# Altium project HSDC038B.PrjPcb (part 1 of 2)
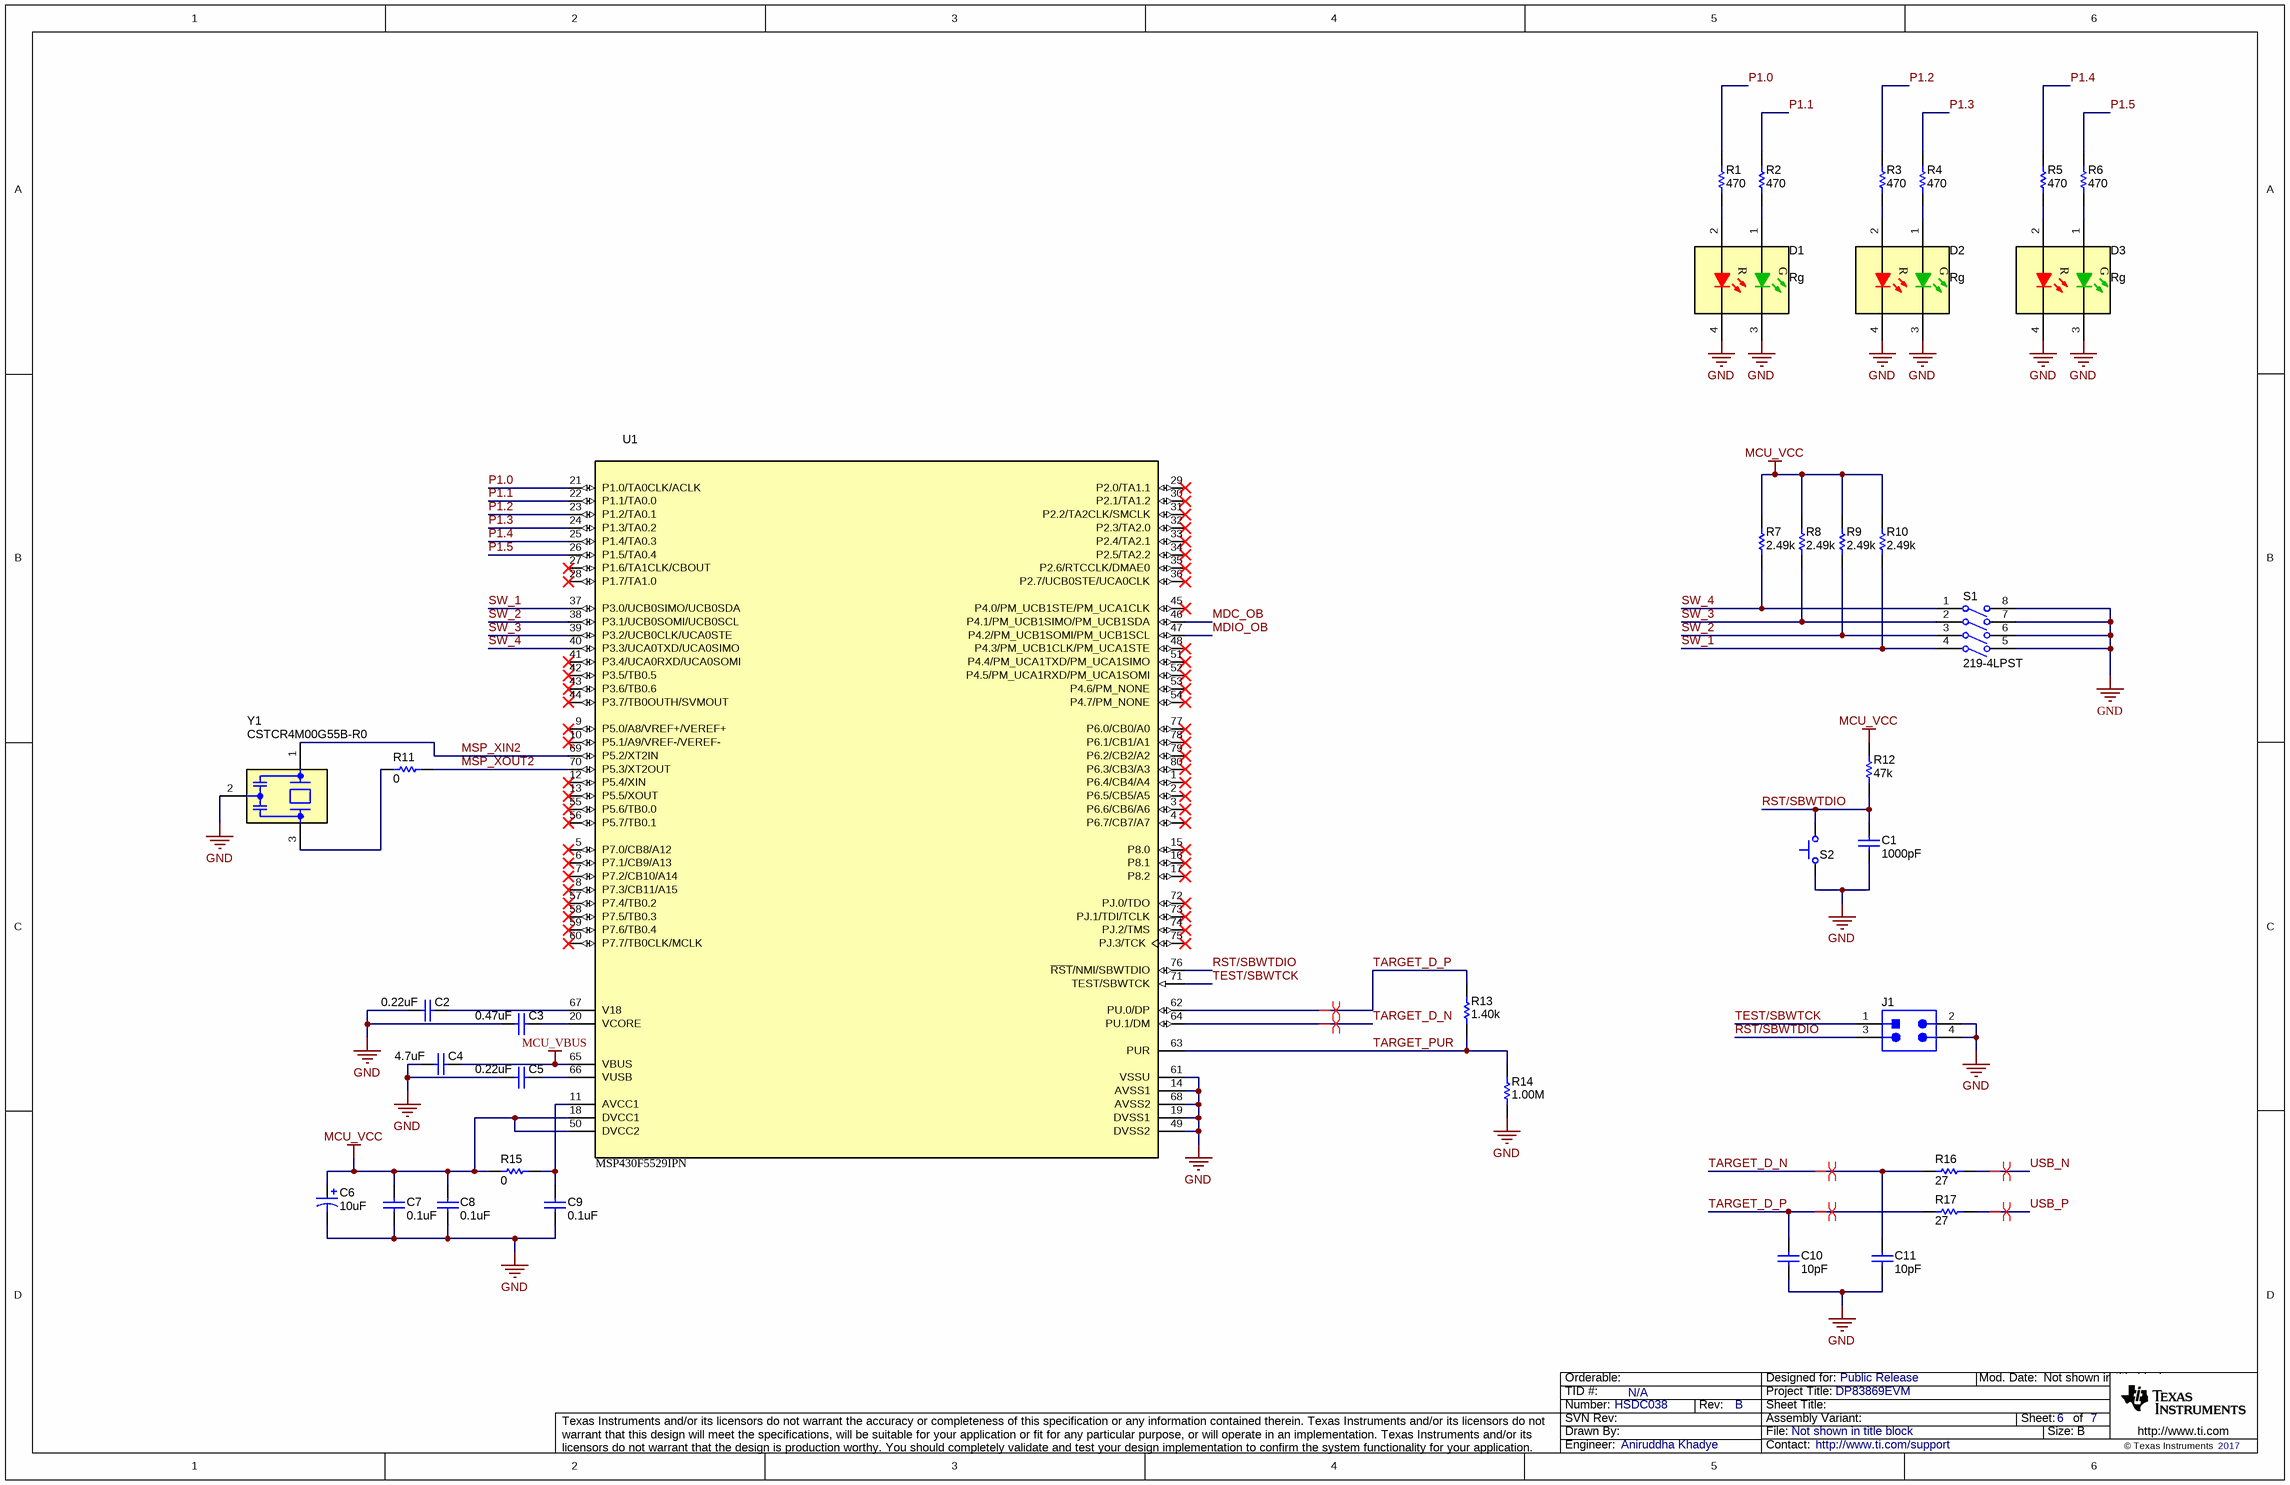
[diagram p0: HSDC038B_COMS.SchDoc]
CopyrightYear: 2017; PCB_Layout: Mitch Morse; PCB_Rev: B; PRJ_Customer: Public Release; PRJ_Engineer: Aniruddha Khadye; PRJ_Number: HSDC038; PRJ_Title: DP83869EVM; SCH_Rev: B; TechSupport: http://www.ti.com/support; TID: N/A
7 sheets, 350 parts. Net scope: global (net labels, ports and power ports of the same name join across sheets).
Board file: HSDC038B.PcbDoc
Sheets:
  HSDC038B_COMS.SchDoc
  HSDC038B_Configuration_Pins.SchDoc
  HSDC038B_CoverSheet.SchDoc
  HSDC038B_DP83869.SchDoc
  HSDC038B_Hardware.SchDoc
  HSDC038B_Magnetics.SchDoc
  HSDC038B_Power_Supply.SchDoc

## Sheet HSDC038B_COMS.SchDoc
size 431 x 279 mm; Date: Not shown in title block; ApprovedBy: Not shown in title block; CheckedBy: Not shown in title block; Author: Not shown in title block; CompanyName: Not shown in title block; Engineer: Not shown in title block; Organization: Not shown in title block; Address1: Not shown in title block; Address2: Not shown in title block; Address3: Not shown in title block; Address4: Not shown in title block; DocumentNumber: 6; Revision: Use project parameter SCH_Rev; SheetNumber: 6; SheetTotal: 7; PageSetup: Record=PageOptions¦CenterHorizontal=True¦CenterVertical=True¦PrintScale=1.00¦XCorrection=1.00¦YCorrection=1.00¦PrintKind=0¦BorderSize=5000000¦LeftOffset=0¦BottomOffset=0¦Orientation=2¦PaperLength=1000¦PaperWidth=1000¦Scale=100¦PaperSource=15¦PrintQuality=600¦MediaType=1¦DitherType=10¦PaperKind=Letter¦PrintScaleMode=1

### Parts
C1  ValueDisplayed: 1000pF  [0402]  (hidden comment: C1005NP01H102J050BA)
C2  ValueDisplayed: 0.22uF  [0603]  (hidden comment: C1608X5R1H224K080AB)
C3  ValueDisplayed: 0.47uF  [0603]  (hidden comment: C1608X6S1H474K080AB)
C4  ValueDisplayed: 4.7uF  [0603]  (hidden comment: C1608X5R1V475K080AC)
C5  ValueDisplayed: 0.22uF  [0603]  (hidden comment: C1608X5R1H224K080AB)
C6  ValueDisplayed: 10uF  [7343-31]  (hidden comment: TPSD106K035R0125)
C7  ValueDisplayed: 0.1uF  [0402]  (hidden comment: GRM155R71C104KA88D)
C8  ValueDisplayed: 0.1uF  [0402]  (hidden comment: GRM155R71C104KA88D)
C9  ValueDisplayed: 0.1uF  [0402]  (hidden comment: GRM155R71C104KA88D)
C10  ValueDisplayed: 10pF  [0603]  (hidden comment: CGA3E2NP01H100D080AA)
C11  ValueDisplayed: 10pF  [0603]  (hidden comment: CGA3E2NP01H100D080AA)
D1  value Rg  [HSMF-C165_RG]  (hidden comment: HSMF-C165)
D2  value Rg  [HSMF-C165_RG]  (hidden comment: HSMF-C165)
D3  value Rg  [HSMF-C165_RG]  (hidden comment: HSMF-C165)
J1  TSW-102-07-G-D  [TSW-102-07-G-D]  (value not drawn)
R1  ValueDisplayed: 470  [0402]  (hidden comment: CRCW0402470RJNED)
R2  ValueDisplayed: 470  [0402]  (hidden comment: CRCW0402470RJNED)
R3  ValueDisplayed: 470  [0402]  (hidden comment: CRCW0402470RJNED)
R4  ValueDisplayed: 470  [0402]  (hidden comment: CRCW0402470RJNED)
R5  ValueDisplayed: 470  [0402]  (hidden comment: CRCW0402470RJNED)
R6  ValueDisplayed: 470  [0402]  (hidden comment: CRCW0402470RJNED)
R7  ValueDisplayed: 2.49k  [0402]  (hidden comment: CRCW04022K49FKED)
R8  ValueDisplayed: 2.49k  [0402]  (hidden comment: CRCW04022K49FKED)
R9  ValueDisplayed: 2.49k  [0402]  (hidden comment: CRCW04022K49FKED)
R10  ValueDisplayed: 2.49k  [0402]  (hidden comment: CRCW04022K49FKED)
R11  ValueDisplayed: 0  [0402]  (hidden comment: CRCW04020000Z0ED)
R12  ValueDisplayed: 47k  [0402]  (hidden comment: CRCW040247K0JNED)
R13  ValueDisplayed: 1.40k  [0402]  (hidden comment: CRCW04021K40FKED)
R14  ValueDisplayed: 1.00M  [0402]  (hidden comment: CRCW04021M00FKED)
R15  ValueDisplayed: 0  [0402]  (hidden comment: CRCW04020000Z0ED)
R16  ValueDisplayed: 27  [0402]  (hidden comment: CRCW040227R0JNED)
R17  ValueDisplayed: 27  [0402]  (hidden comment: CRCW040227R0JNED)
S1  219-4LPST  [SW_219-4LPST]
S2  KSR221GLFS  [KSR]  (value not drawn)
U1  MSP430F5529IPN  [PN0080A_N]
Y1  CSTCR4M00G55B-R0  [Murata_CSTCR_G]

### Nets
GND: C1.1 C2.2 C3.2 C4.1 C5.2 C6.2(-) C7.1 C8.1 C9.1 C10.1 C11.1 D1.3(K) D1.4(K) D2.3(K) D2.4(K) D3.3(K) D3.4(K) J1.2 J1.4 R14.2 S1.5(B4) S1.6(B3) S1.7(B2) S1.8(B1) S2.1 U1.14(AVSS1) U1.19(DVSS1) U1.49(DVSS2) U1.61(VSSU) U1.68(AVSS2) Y1.2(GND)
MCU_VBUS: C4.2 U1.65(VBUS)
MCU_VCC: C6.1(+) C7.2 C8.2 R7.1 R8.1 R9.1 R10.1 R12.1 R15.1 U1.18(DVCC1) U1.50(DVCC2)
MDC_OB: U1.46(P4.1/PM_UCB1SIMO/PM_UCB1SDA)
MDIO_OB: U1.47(P4.2/PM_UCB1SOMI/PM_UCB1SCL)
MSP_XIN2: U1.69(P5.2/XT2IN) Y1.1(In)
MSP_XOUT2: R11.2 U1.70(P5.3/XT2OUT)
P1.0: R1.2 U1.21(P1.0/TA0CLK/ACLK)
P1.1: R2.2 U1.22(P1.1/TA0.0)
P1.2: R3.2 U1.23(P1.2/TA0.1)
P1.3: R4.2 U1.24(P1.3/TA0.2)
P1.4: R5.2 U1.25(P1.4/TA0.3)
P1.5: R6.2 U1.26(P1.5/TA0.4)
RST/SBWTDIO: C1.2 J1.3 R12.2 S2.2 U1.76(~{RST}/NMI/SBWTDIO)
SW_1: R10.2 S1.4(A4) U1.37(P3.0/UCB0SIMO/UCB0SDA)
SW_2: R9.2 S1.3(A3) U1.38(P3.1/UCB0SOMI/UCB0SCL)
SW_3: R8.2 S1.2(A2) U1.39(P3.2/UCB0CLK/UCA0STE)
SW_4: R7.2 S1.1(A1) U1.40(P3.3/UCA0TXD/UCA0SIMO)
TARGET_D_N: C11.2 R16.1 U1.64(PU.1/DM)
TARGET_D_P: C10.2 R13.2 R17.1 U1.62(PU.0/DP)
TARGET_PUR: R13.1 R14.1 U1.63(PUR)
TEST/SBWTCK: J1.1 U1.71(TEST/SBWTCK)
USB_N: R16.2
USB_P: R17.2
NetC2_1: C2.1 U1.67(V18)
NetC3_1: C3.1 U1.20(VCORE)
NetC5_1: C5.1 U1.66(VUSB)
NetC9_2: C9.2 R15.2 U1.11(AVCC1)
NetD1_1: D1.1(A) R2.1
NetD1_2: D1.2(A) R1.1
NetD2_1: D2.1(A) R4.1
NetD2_2: D2.2(A) R3.1
NetD3_1: D3.1(A) R6.1
NetD3_2: D3.2(A) R5.1
NetR11_1: R11.1 Y1.3(Out)

Not connected (* = marked no-connect by the designer): U1 1(P6.4/CB4/A4)* 2(P6.5/CB5/A5)* 3(P6.6/CB6/A6)* 4(P6.7/CB7/A7)* 5(P7.0/CB8/A12)* 6(P7.1/CB9/A13)* 7(P7.2/CB10/A14)* 8(P7.3/CB11/A15)* 9(P5.0/A8/VREF+/VEREF+)* 10(P5.1/A9/VREF-/VEREF-)* 12(P5.4/XIN)* 13(P5.5/XOUT)* 15(P8.0)* 16(P8.1)* 17(P8.2)* 27(P1.6/TA1CLK/CBOUT)* 28(P1.7/TA1.0)* 29(P2.0/TA1.1)* 30(P2.1/TA1.2)* 31(P2.2/TA2CLK/SMCLK)* 32(P2.3/TA2.0)* 33(P2.4/TA2.1)* 34(P2.5/TA2.2)* 35(P2.6/RTCCLK/DMAE0)* 36(P2.7/UCB0STE/UCA0CLK)* 41(P3.4/UCA0RXD/UCA0SOMI)* 42(P3.5/TB0.5)* 43(P3.6/TB0.6)* 44(P3.7/TB0OUTH/SVMOUT)* 45(P4.0/PM_UCB1STE/PM_UCA1CLK)* 48(P4.3/PM_UCB1CLK/PM_UCA1STE)* 51(P4.4/PM_UCA1TXD/PM_UCA1SIMO)* 52(P4.5/PM_UCA1RXD/PM_UCA1SOMI)* 53(P4.6/PM_NONE)* 54(P4.7/PM_NONE)* 55(P5.6/TB0.0)* 56(P5.7/TB0.1)* 57(P7.4/TB0.2)* 58(P7.5/TB0.3)* 59(P7.6/TB0.4)* 60(P7.7/TB0CLK/MCLK)* 72(PJ.0/TDO)* 73(PJ.1/TDI/TCLK)* 74(PJ.2/TMS)* 75(PJ.3/TCK)* 77(P6.0/CB0/A0)* 78(P6.1/CB1/A1)* 79(P6.2/CB2/A2)* 80(P6.3/CB3/A3)*

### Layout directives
differential pair: TARGET_D_N, TARGET_D_P, USB_N, USB_P

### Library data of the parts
C1 = CMP-0006254-2: CAP, CERM, 1000 pF, 50 V, +/- 5%, C0G/NP0, 0402; Manufacturer: TDK; Polarized: N; Value: 1000pF; U/M: EA; Cap_F: 1nF; Value1: Unknown; VDC_V: 50V; TaMin_C: -55°C; TaMax_C: 150°C; SizeArea_mm2: 0.5; SizeAreaWB_mm2: 3; SizeX_mm: 1; SizeZ_mm: 0.6; AEC Category: Q200
C2 C5 = CMP-0007013-5: CAP, CERM, 0.22 uF, 50 V, +/- 10%, X5R, 0603; Manufacturer: TDK; Polarized: N; Value: 0.22uF; U/M: EA; Cap_F: 220nF; ESR_ohm: 0.021699; Value1: 0.021699 ohm; VDC_V: 50V; IRMS_A: 1.12496A; TaMin_C: -55°C; TaMax_C: 85°C; SizeArea_mm2: 1.28; SizeAreaWB_mm2: 4.68; SizeX_mm: 1.6; SizeY_mm: 0.8; SizeZ_mm: 1; AEC Category: Q200
C3 = CMP-0007033-4: CAP, CERM, 0.47 uF, 50 V, +/- 10%, X6S, 0603; Manufacturer: TDK; Polarized: N; Value: 0.47uF; U/M: EA; Cap_F: 470nF; ESR_ohm: 0.010974; Value1: 0.010974 ohm; VDC_V: 50V; IRMS_A: 1.57483A; TaMin_C: -55°C; TaMax_C: 105°C; SizeArea_mm2: 1.28; SizeAreaWB_mm2: 4.68; SizeX_mm: 1.6; SizeY_mm: 0.8; SizeZ_mm: 1; AEC Category: Q200
C4 = CMP-0007022-5: CAP, CERM, 4.7 uF, 35 V, +/- 10%, X5R, 0603; Manufacturer: TDK; Polarized: N; Value: 4.7uF; U/M: EA; Cap_F: 4.7µF; ESR_ohm: 3.728m; Value1: 0.003728 ohm; VDC_V: 35V; IRMS_A: 2.69359A; TaMin_C: -55°C; TaMax_C: 85°C; SizeArea_mm2: 1.28; SizeAreaWB_mm2: 4.68; SizeX_mm: 1.6; SizeY_mm: 0.8; SizeZ_mm: 1; AEC Category: Q200
C6 = CMP-0011855-2: CAP, TA, 10 uF, 35 V, +/- 10%, 0.125 ohm, SMD; Manufacturer: AVX; Polarized: Y; CompType: Capacitor; Value: 10uF; U/M: EA; Cap_F: 10µF; VDC_V: 35V; ESR_ohm: 1.25d; IRMS_A: 9.86dA; TaMin_C: -55°C; TaMax_C: 125°C; Cap_Case: D; AEC Category: Q200; SizeArea_mm2: 31.39; SizeAreaWB_mm2: 58.59; SizeX_mm: 7.3; SizeY_mm: 4.3; SizeZ_mm: 3.1
C7-C9 = CMP-0006641-2: CAP, CERM, 0.1 uF, 16 V, +/- 10%, X7R, 0402; Manufacturer: MuRata; Polarized: N; Value: 0.1uF; U/M: EA; Cap_F: 100nF; Value1: Unknown; VDC_V: 16V; TaMin_C: -55°C; TaMax_C: 125°C; AEC Category: Q200; SizeArea_mm2: 0.5; SizeAreaWB_mm2: 3; SizeX_mm: 1; SizeZ_mm: 0.6
C10 C11 = CMP-0007074-4: CAP, CERM, 10 pF, 50 V, +/- 5%, C0G/NP0, 0603; Manufacturer: TDK; Polarized: N; Value: 10pF; U/M: EA; Value1: Unknown; VDC_V: 50V; TaMin_C: -55°C; TaMax_C: 150°C; SizeArea_mm2: 1.28; SizeAreaWB_mm2: 4.68; SizeX_mm: 1.6; SizeY_mm: 0.8; SizeZ_mm: 1; AEC Category: Q200
D1-D3 = CMP-0002934-2: LED, Rg, SMD; Manufacturer: Avago; Vf_V: 2.2V; Io_A: 20mA; Vr_V: 5V; Ir_A: 100µA; Tjmax_C: 85°C; Value1: W; LuminousIntensity_IV: 20; Angle: 120; U/M: EA
J1 = CMP-0075404-1: Header, 100mil, 2x2, Gold, TH; Manufacturer: Samtec; Pitch_mm: 2.54; Gender: Male; Shrouded: N; Row_Count: 2; Current_A: 6.3A; Voltage_V: 550V; Cert_CSA: Y; CNHeader: True; CT: False; Green_Lifecycle: Active; Green_REACh: Passed
R1-R6 = CMP-0026934-3: RES, 470, 5%, 0.063 W, AEC-Q200 Grade 0, 0402; Manufacturer: Vishay-Dale; Value: 470; Value_Code: 470R; Power_W: 63mW; Value2: 0.063W; VDC_V: 50V; TempCo: 200 ppm/C; EIA_Code: E24; AEC Category: Q200; AEC Grade: 0; AEC Qualified: Y; SizeArea_mm2: 0.5; SizeX_mm: 1; SizeZ_mm: 0.6
R7-R10 = CMP-0026237-2: RES, 2.49 k, 1%, 0.063 W, AEC-Q200 Grade 0, 0402; Manufacturer: Vishay-Dale; Value: 2.49k; Value_Code: 2k49; Power_W: 63mW; Value2: 0.063W; VDC_V: 50V; TempCo: 100 ppm/C; EIA_Code: E96; AEC Category: Q200; AEC Qualified: Y; AEC Grade: 0; SizeArea_mm2: 0.5; SizeX_mm: 1; SizeZ_mm: 0.6
R11 R15 = CMP-0026822-3: RES, 0, 5%, 0.063 W, AEC-Q200 Grade 0, 0402; Manufacturer: Vishay-Dale; Value: 0; Value_Code: 0000; Power_W: 63mW; Value2: 0.063W; VDC_V: 50V; TempCo: 200 ppm/C; EIA_Code: E24; AEC Category: Q200; AEC Qualified: Y; SizeArea_mm2: 0.5; SizeX_mm: 1; SizeZ_mm: 0.6
R12 = CMP-0026935-3: RES, 47 k, 5%, 0.063 W, AEC-Q200 Grade 0, 0402; Manufacturer: Vishay-Dale; Value: 47k; Value_Code: 47k0; Power_W: 63mW; Value2: 0.063W; VDC_V: 50V; TempCo: 200 ppm/C; EIA_Code: E24; AEC Category: Q200; AEC Qualified: Y; AEC Grade: 0; SizeArea_mm2: 0.5; SizeX_mm: 1; SizeZ_mm: 0.6
R13 = CMP-0026085-3: RES, 1.40 k, 1%, 0.063 W, AEC-Q200 Grade 0, 0402; Manufacturer: Vishay-Dale; Value: 1.40k; Res_ohm: 1.4k; Value_Code: 1k40; Power_W: 63mW; Value2: 0.063W; VDC_V: 50V; TempCo: 100 ppm/C; EIA_Code: E96; AEC Category: Q200; AEC Qualified: Y; AEC Grade: 0; SizeArea_mm2: 0.5; SizeX_mm: 1; SizeZ_mm: 0.6
R14 = CMP-0026100-2: RES, 1.00 M, 1%, 0.063 W, AEC-Q200 Grade 0, 0402; Manufacturer: Vishay-Dale; Value: 1.00Meg; Res_ohm: 1M; Value_Code: 1M00; Power_W: 63mW; Value2: 0.063W; VDC_V: 50V; TempCo: 100 ppm/C; EIA_Code: E96; AEC Category: Q200; AEC Qualified: Y; AEC Grade: 0; SizeArea_mm2: 0.5; SizeX_mm: 1; SizeZ_mm: 0.6
R16 R17 = CMP-0026888-3: RES, 27, 5%, 0.063 W, AEC-Q200 Grade 0, 0402; Manufacturer: Vishay-Dale; Value: 27; Value_Code: 27R0; Power_W: 63mW; Value2: 0.063W; VDC_V: 50V; TempCo: 200 ppm/C; EIA_Code: E24; AEC Category: Q200; AEC Qualified: Y; AEC Grade: 0; SizeArea_mm2: 0.5; SizeX_mm: 1; SizeZ_mm: 0.6
S1 = CMP-0002176-2: Switch, SPST 4 Pos, Top Actuated, SMT; Manufacturer: CTS Electrocomponents; VDC_V: 50V; SwitchFunction: Off-On; PositionCount: 4; CurrentRating_mA: 100A
S2 = CMP-0002170-2: Switch, Normally open, 2.3N force, 200k operations, SMD; Manufacturer: C&K Components; Circuit: SPST Switch; VDC_V: 32V; SwitchFunction: Off-Mom; PositionCount: 1; CurrentRating_mA: 1.001kA
U1 = CMP-0038965-1: 25 MHz Mixed Signal Microcontroller with 128 KB Flash, 8192 B SRAM and 63 GPIOs, -40 to 85 degC, 80-pin QFP (PN), Green (RoHS & no Sb/Br); Manufacturer: Texas Instruments; ADC: 12-bit SAR; ADC Channels: 16; Brown Out Reset: Yes; DMA: 3; Flash(KB): 128; Frequency(MHz): 25; GPIO: 63; Multiplier: 32x32; SRAM(B): 8192; SubFamily: 5 Series; Timers - 16-bit: 4; USB: 1; USCI_A (UART/LIN/IrDA/SPI): 2
Y1 = CMP-0084387-1: Resonator, 4 MHz, 39 pF, AEC-Q200 Grade 1, SMD; Manufacturer: MuRata; SizeAreaWB_mm2: 16.5; SizeArea_mm2: 9; SizeX_mm: 4.5; SizeY_mm: 2; SizeZ_mm: 1.2; TaMin_C: -40°C; TaMax_C: 125°C; Frequency_Fixed: 4MHz; AEC Category: Q200; AEC Grade: 1; AEC Qualified: Y; Load Capacitance: 39 pF

## Sheet HSDC038B_Configuration_Pins.SchDoc
size 431 x 279 mm; Date: Not shown in title block; ApprovedBy: Not shown in title block; CheckedBy: Not shown in title block; Author: Not shown in title block; CompanyName: Not shown in title block; Engineer: Not shown in title block; Organization: Not shown in title block; Address1: Not shown in title block; Address2: Not shown in title block; Address3: Not shown in title block; Address4: Not shown in title block; DocumentNumber: 3; Revision: Use project parameter SCH_Rev; SheetNumber: 3; SheetTotal: 7; PageSetup: Record=PageOptions¦CenterHorizontal=True¦CenterVertical=True¦PrintScale=1.00¦XCorrection=1.00¦YCorrection=1.00¦PrintKind=0¦BorderSize=5000000¦LeftOffset=0¦BottomOffset=0¦Orientation=2¦PaperLength=1000¦PaperWidth=1000¦Scale=100¦PaperSource=15¦PrintQuality=600¦MediaType=1¦DitherType=10¦PaperKind=Letter¦PrintScaleMode=1
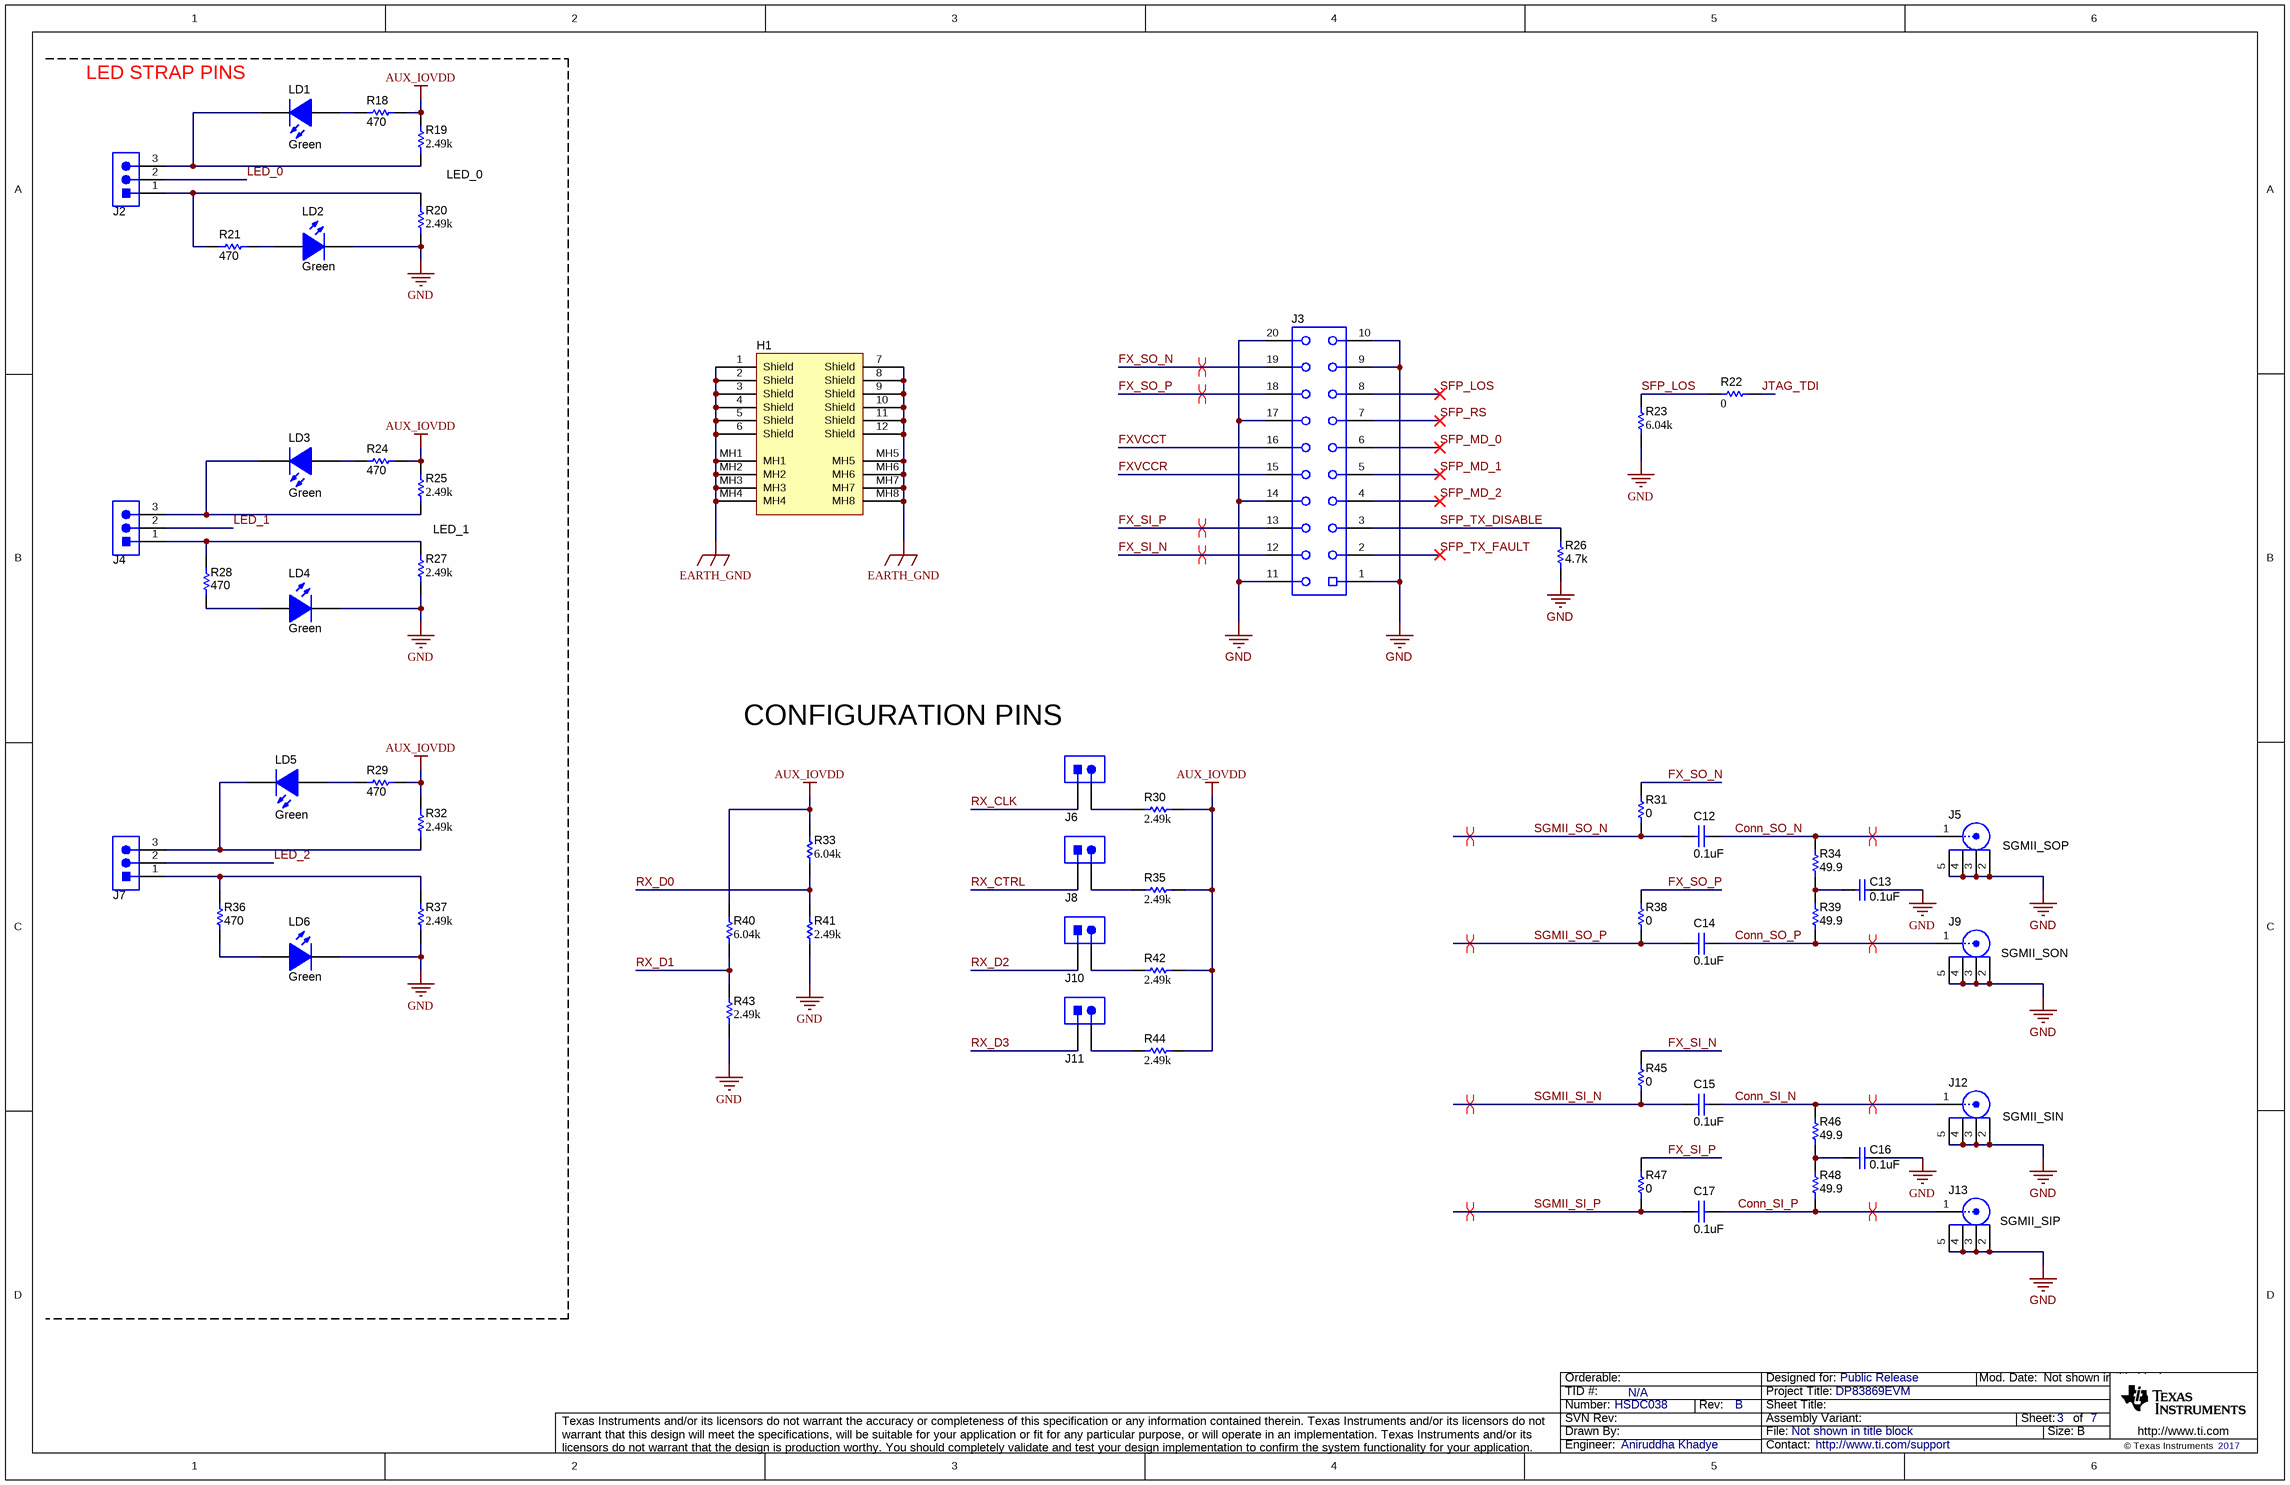
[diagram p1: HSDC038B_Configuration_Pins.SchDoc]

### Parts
C12  ValueDisplayed: 0.1uF  [0402_065]  (hidden comment: 160R07X104KV4T)
C13  ValueDisplayed: 0.1uF  [0402]  (hidden comment: GRM155R71C104KA88D)
C14  ValueDisplayed: 0.1uF  [0402_065]  (hidden comment: 160R07X104KV4T)
C15  ValueDisplayed: 0.1uF  [0402_065]  (hidden comment: 160R07X104KV4T)
C16  ValueDisplayed: 0.1uF  [0402]  (hidden comment: GRM155R71C104KA88D)
C17  ValueDisplayed: 0.1uF  [0402_065]  (hidden comment: 160R07X104KV4T)
H1  U77-A1118-200T  [Amphenol_U77-A1118-200T]  (value not drawn)
J2  HTSW-103-07-G-S  [Samtec_HTSW-103-07-G-S]  (value not drawn)
J3  1367073-1  [TE_1367073-1]  (value not drawn)
J4  HTSW-103-07-G-S  [Samtec_HTSW-103-07-G-S]  (value not drawn)
J5  901-143-6RFX  [Amphenol_901-143-6RFX]  (value not drawn)
J6  HTSW-102-07-G-S  [Samtec_HTSW-102-07-G-S]  (value not drawn)
J7  HTSW-103-07-G-S  [Samtec_HTSW-103-07-G-S]  (value not drawn)
J8  HTSW-102-07-G-S  [Samtec_HTSW-102-07-G-S]  (value not drawn)
J9  901-143-6RFX  [Amphenol_901-143-6RFX]  (value not drawn)
J10  HTSW-102-07-G-S  [Samtec_HTSW-102-07-G-S]  (value not drawn)
J11  HTSW-102-07-G-S  [Samtec_HTSW-102-07-G-S]  (value not drawn)
J12  901-143-6RFX  [Amphenol_901-143-6RFX]  (value not drawn)
J13  901-143-6RFX  [Amphenol_901-143-6RFX]  (value not drawn)
LD1  value Green  [QTLP630C_Green]  (hidden comment: QTLP630C4TR)
LD2  value Green  [QTLP630C_Green]  (hidden comment: QTLP630C4TR)
LD3  value Green  [QTLP630C_Green]  (hidden comment: QTLP630C4TR)
LD4  value Green  [QTLP630C_Green]  (hidden comment: QTLP630C4TR)
LD5  value Green  [QTLP630C_Green]  (hidden comment: QTLP630C4TR)
LD6  value Green  [QTLP630C_Green]  (hidden comment: QTLP630C4TR)
R18  ValueDisplayed: 470  [0603]  (hidden comment: RC0603FR-07470RL)
R19  ValueDisplayed: 2.49k  [0402]  (hidden comment: CRCW04022K49FKED)
R20  ValueDisplayed: 2.49k  [0402]  (hidden comment: CRCW04022K49FKED)
R21  ValueDisplayed: 470  [0603]  (hidden comment: RC0603FR-07470RL)
R22  ValueDisplayed: 0  [0402]  (hidden comment: ERJ-2GE0R00X)
R23  ValueDisplayed: 6.04k  [0402]  (hidden comment: CRCW04026K04FKED)
R24  ValueDisplayed: 470  [0603]  (hidden comment: RC0603FR-07470RL)
R25  ValueDisplayed: 2.49k  [0402]  (hidden comment: CRCW04022K49FKED)
R26  ValueDisplayed: 4.7k  [0402]  (hidden comment: CRCW04024K70JNED)
R27  ValueDisplayed: 2.49k  [0402]  (hidden comment: CRCW04022K49FKED)
R28  ValueDisplayed: 470  [0603]  (hidden comment: RC0603FR-07470RL)
R29  ValueDisplayed: 470  [0603]  (hidden comment: RC0603FR-07470RL)
R30  ValueDisplayed: 2.49k  [0402]  (hidden comment: CRCW04022K49FKED)
R31  ValueDisplayed: 0  [0402]  (hidden comment: MCR01MZPJ000)
R32  ValueDisplayed: 2.49k  [0402]  (hidden comment: CRCW04022K49FKED)
R33  ValueDisplayed: 6.04k  [0402]  (hidden comment: CRCW04026K04FKED)
R34  ValueDisplayed: 49.9  [0402L]  (hidden comment: CRCW040249R9FKED)
R35  ValueDisplayed: 2.49k  [0402]  (hidden comment: CRCW04022K49FKED)
R36  ValueDisplayed: 470  [0603]  (hidden comment: RC0603FR-07470RL)
R37  ValueDisplayed: 2.49k  [0402]  (hidden comment: CRCW04022K49FKED)
R38  ValueDisplayed: 0  [0402]  (hidden comment: MCR01MZPJ000)
R39  ValueDisplayed: 49.9  [0402L]  (hidden comment: CRCW040249R9FKED)
R40  ValueDisplayed: 6.04k  [0402]  (hidden comment: CRCW04026K04FKED)
R41  ValueDisplayed: 2.49k  [0402]  (hidden comment: CRCW04022K49FKED)
R42  ValueDisplayed: 2.49k  [0402]  (hidden comment: CRCW04022K49FKED)
R43  ValueDisplayed: 2.49k  [0402]  (hidden comment: CRCW04022K49FKED)
R44  ValueDisplayed: 2.49k  [0402]  (hidden comment: CRCW04022K49FKED)
R45  ValueDisplayed: 0  [0402]  (hidden comment: MCR01MZPJ000)
R46  ValueDisplayed: 49.9  [0402L]  (hidden comment: CRCW040249R9FKED)
R47  ValueDisplayed: 0  [0402]  (hidden comment: MCR01MZPJ000)
R48  ValueDisplayed: 49.9  [0402L]  (hidden comment: CRCW040249R9FKED)

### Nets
AUX_IOVDD: R18.1 R19.2 R24.1 R25.2 R29.1 R30.2 R32.2 R33.2 R35.2 R40.2 R42.2 R44.2
EARTH_GND: H1.1(Shield) H1.2(Shield) H1.3(Shield) H1.4(Shield) H1.5(Shield) H1.6(Shield) H1.7(Shield) H1.8(Shield) H1.9(Shield) H1.10(Shield) H1.11(Shield) H1.12(Shield) H1.MH1 H1.MH2 H1.MH3 H1.MH4 H1.MH5 H1.MH6 H1.MH7 H1.MH8
FXVCCR: J3.15
FXVCCT: J3.16
GND: C13.2 C16.2 J3.1 J3.9 J3.10 J3.11 J3.14 J3.17 J3.20 J5.2 J5.3 J5.4 J5.5 J9.2 J9.3 J9.4 J9.5 J12.2 J12.3 J12.4 J12.5 J13.2 J13.3 J13.4 J13.5 LD2.2(K) LD4.2(K) LD6.2(K) R20.1 R23.1 R26.1 R27.1 R37.1 R41.1 R43.1
Conn_SI_N: C15.1 J12.1 R46.2
Conn_SI_P: C17.1 J13.1 R48.1
Conn_SO_N: C12.1 J5.1 R34.2
Conn_SO_P: C14.1 J9.1 R39.1
FX_SI_N: J3.12 R45.2
FX_SI_P: J3.13 R47.2
FX_SO_N: J3.19 R31.2
FX_SO_P: J3.18 R38.2
JTAG_TDI: R22.2
LED_0: J2.2
LED_1: J4.2
LED_2: J7.2
RX_CLK: J6.1
RX_CTRL: J8.1
RX_D0: R33.1 R41.2
RX_D1: R40.1 R43.2
RX_D2: J10.1
RX_D3: J11.1
SFP_LOS: J3.8 R22.1 R23.2
SFP_MD_0: J3.6
SFP_MD_1: J3.5
SFP_MD_2: J3.4
SFP_RS: J3.7
SFP_TX_DISABLE: J3.3 R26.2
SFP_TX_FAULT: J3.2
SGMII_SI_N: C15.2 R45.1
SGMII_SI_P: C17.2 R47.1
SGMII_SO_N: C12.2 R31.1
SGMII_SO_P: C14.2 R38.1
NetC13_1: C13.1 R34.1 R39.2
NetC16_1: C16.1 R46.1 R48.2
NetJ2_1: J2.1 R20.2 R21.1
NetJ2_3: J2.3 LD1.2(K) R19.1
NetJ4_1: J4.1 R27.2 R28.2
NetJ4_3: J4.3 LD3.2(K) R25.1
NetJ6_2: J6.2 R30.1
NetJ7_1: J7.1 R36.2 R37.2
NetJ7_3: J7.3 LD5.2(K) R32.1
NetJ8_2: J8.2 R35.1
NetJ10_2: J10.2 R42.1
NetJ11_2: J11.2 R44.1
NetLD1_1: LD1.1(A) R18.2
NetLD2_1: LD2.1(A) R21.2
NetLD3_1: LD3.1(A) R24.2
NetLD4_1: LD4.1(A) R28.1
NetLD5_1: LD5.1(A) R29.2
NetLD6_1: LD6.1(A) R36.1

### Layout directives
differential pair: Conn_SI_N, Conn_SI_P, Conn_SO_N, Conn_SO_P, FX_SI_N, FX_SI_P, FX_SO_N, FX_SO_P, SGMII_SI_N, SGMII_SI_P, SGMII_SO_N, SGMII_SO_P

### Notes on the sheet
- LED STRAP PINS
- LED_0
- LED_1
- CONFIGURATION PINS
- (near J5) SGMII_SOP
- (near J9) SGMII_SON
- (near J12) SGMII_SIN
- (near J13) SGMII_SIP

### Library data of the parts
C12 C14 C15 C17 = CMP-0006204-2: CAP, CERM, 0.1 uF, 16 V, +/- 10%, X5R, 0402; Manufacturer: Johanson Technology; TaMin_C: -55°C; Polarized: N; SizeAreaWB_mm2: 3; Value1: Unknown; U/M: EA; Value: 0.1uF; TaMax_C: 85°C; SizeZ_mm: 0.65; SizeX_mm: 1; SizeY_mm: 0.5; Cap_Case: 0402; Value2: 16V; CompType: Capacitor; Cap_F: 100nF; AEC Category: Q200
C13 C16 = CMP-0006641-2: as C7 on sheet HSDC038B_COMS
H1 = CMP-0003774-1: SFP Single Cage; Manufacturer: Amphenol Canada
J2 J4 J7 = CMP-0075484-1: Header, 100mil, 3x1, Gold, TH; Manufacturer: Samtec; Green_REACh: Passed; CT: False; Green_Lifecycle: Active; CNHeader: True
J3 = CMP-0054875-1: Receptacle, 0.8mm, 10x2, Gold, R/A, SMT; Manufacturer: TE Connectivity; CNHeader: FALSE; Gender: Female; Pitch_mm: 0.8; Row_Count: 2; RowSpacing_mm: 8.2
J5 J9 J12 J13 = CMP-0055851-2: JACK, SMA, 50 Ohm, Gold, R/A, TH; Manufacturer: Amphenol RF; Gender: Female
J6 J8 J10 J11 = CMP-0075483-1: Header, 100mil, 2x1, Gold, TH; Manufacturer: Samtec; Green_REACh: Passed; CT: False; Green_Lifecycle: Active; CNHeader: True
LD1-LD6 = CMP-0002917-1: LED, Green, SMD; Manufacturer: Everlight; Vf_V: 2.1V; Io_A: 20mA; Vr_V: 5V; Tjmax_C: 85°C; Value1: W; Angle: 140; U/M: EA
R18 R21 R24 R28 R29 R36 = CMP-0023129-3: RES, 470, 1%, 0.1 W, 0603; Manufacturer: Yageo America; Value: 470; Value_Code: 470R; Power_W: 100mW; Value2: 0.1W; VDC_V: 150V; TempCo: 200 ppm/C; U/M: EA; AEC Category: Q200; SizeArea_mm2: 1.28; SizeX_mm: 1.6; SizeY_mm: 0.8; SizeZ_mm: 1
R19 R20 R25 R27 R30 R32 R35 R37 R41-R44 = CMP-0026237-2: RES, 2.49 k, 1%, 0.063 W, AEC-Q200 Grade 0, 0402; Manufacturer: Vishay-Dale; Power_W: 63mW; TempCo: 100 ppm/C; Value_Code: 2k49; Value: 2.49k; EIA_Code: E96; SizeX_mm: 1; SizeY_mm: 0.5; SizeZ_mm: 0.6; Value2: 0.063W; AEC Qualified: Y; VDC_V: 50V; AEC Grade: 0; AEC Category: Q200
R22 = CMP-0026992-2: RES, 0, 5%, 0.063 W, 0402; Manufacturer: Panasonic; Value: 0; Value_Code: 0000; Power_W: 63mW; Value2: 0.063W; VDC_V: 50V; TempCo: 600 ppm/C; EIA_Code: E24; U/M: EA; AEC Category: Q200; SizeArea_mm2: 0.5; SizeX_mm: 1; SizeZ_mm: 0.6
R23 R33 R40 = CMP-0026512-2: RES, 6.04 k, 1%, 0.063 W, AEC-Q200 Grade 0, 0402; Manufacturer: Vishay-Dale; Power_W: 63mW; TempCo: 100 ppm/C; Value_Code: 6k04; Value: 6.04k; EIA_Code: E96; SizeX_mm: 1; SizeY_mm: 0.5; SizeZ_mm: 0.6; Value2: 0.063W; AEC Qualified: Y; VDC_V: 50V; AEC Grade: 0; AEC Category: Q200
R26 = CMP-0026938-5: RES, 4.7 k, 5%, 0.063 W, AEC-Q200 Grade 0, 0402; Manufacturer: Vishay-Dale; Power_W: 63mW; TempCo: 200 ppm/C; Value_Code: 4k70; Value: 4.7k; EIA_Code: E24; SizeX_mm: 1; SizeY_mm: 0.5; SizeZ_mm: 0.6; Value2: 0.063W; AEC Qualified: Y; VDC_V: 50V; AEC Category: Q200; AEC Grade: 0
R31 R38 R45 R47 = CMP-0027002-2: RES, 0, 5%, 0.063 W, 0402; Manufacturer: Rohm; Power_W: 63mW; TempCo: 500 ppm/C; Value_Code: 0000; U/M: EA; Value: 0; EIA_Code: E24; SizeX_mm: 1; SizeY_mm: 0.5; SizeZ_mm: 0.6; Value2: 0.063W; VDC_V: 50V; AEC Category: Q200
R34 R39 R46 R48 = CMP-0026404-2: RES, 49.9, 1%, 0.063 W, AEC-Q200 Grade 0, 0402; Manufacturer: Vishay-Dale; Value: 49.9; Value_Code: 49R9; Power_W: 63mW; Value2: 0.063W; VDC_V: 50V; TempCo: 100 ppm/C; EIA_Code: E96; AEC Category: Q200; AEC Grade: 0; AEC Qualified: Y; SizeArea_mm2: 0.5; SizeX_mm: 1; SizeZ_mm: 0.6

## Sheet HSDC038B_CoverSheet.SchDoc
size 431 x 279 mm; Date: Not shown in title block; ApprovedBy: Not shown in title block; CheckedBy: Not shown in title block; Author: Not shown in title block; CompanyName: Not shown in title block; Engineer: Not shown in title block; Organization: Not shown in title block; Address1: Not shown in title block; Address2: Not shown in title block; Address3: Not shown in title block; Address4: Not shown in title block; DocumentNumber: 1; Revision: Use project parameter SCH_Rev; SheetNumber: 1; SheetTotal: 7; PageSetup: Record=PageOptions¦CenterHorizontal=True¦CenterVertical=True¦PrintScale=1.00¦XCorrection=1.00¦YCorrection=1.00¦PrintKind=0¦BorderSize=5000000¦LeftOffset=0¦BottomOffset=0¦Orientation=2¦PaperLength=1000¦PaperWidth=1000¦Scale=100¦PaperSource=15¦PrintQuality=600¦MediaType=1¦DitherType=10¦PaperKind=Letter¦PrintScaleMode=1
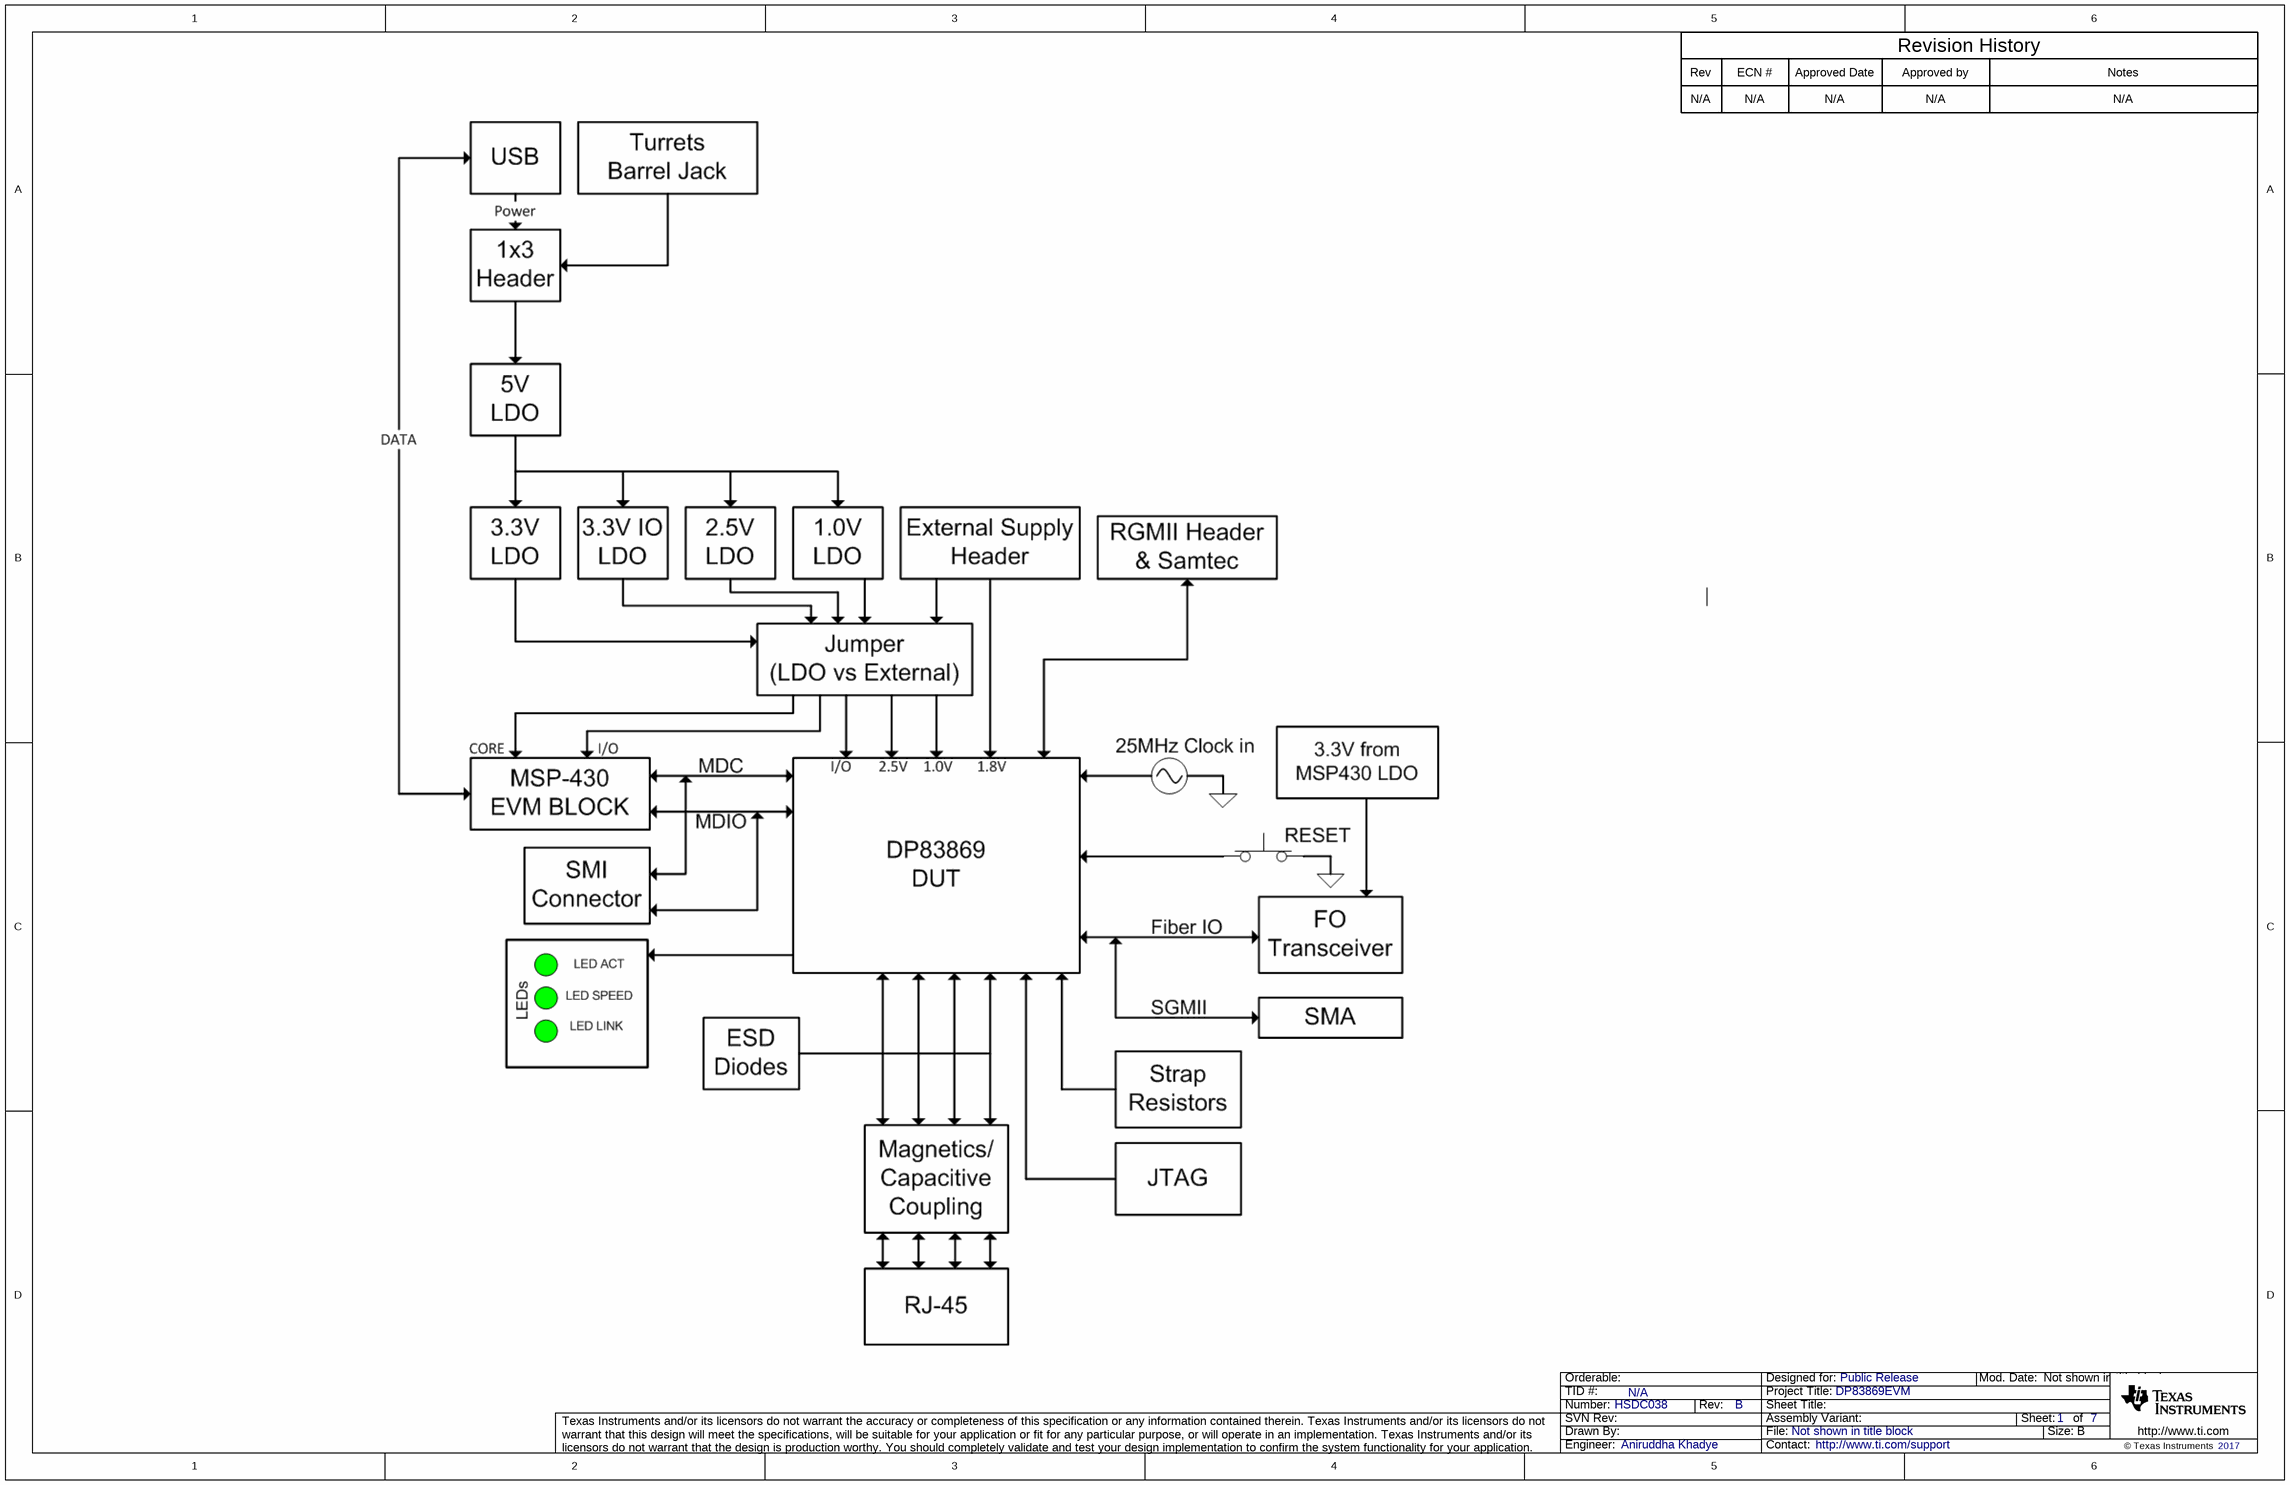
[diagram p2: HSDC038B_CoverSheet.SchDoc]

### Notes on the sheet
- Rev
- N/A
- ECN #
- Approved Date
- Approved by
- Revision History
- Notes

## Sheet HSDC038B_DP83869.SchDoc
size 431 x 279 mm; Date: Not shown in title block; ApprovedBy: Not shown in title block; CheckedBy: Not shown in title block; Author: Not shown in title block; CompanyName: Not shown in title block; Engineer: Not shown in title block; Organization: Not shown in title block; Address1: Not shown in title block; Address2: Not shown in title block; Address3: Not shown in title block; Address4: Not shown in title block; DocumentNumber: 2; Revision: Use project parameter SCH_Rev; SheetNumber: 2; SheetTotal: 7; PageSetup: Record=PageOptions¦CenterHorizontal=True¦CenterVertical=True¦PrintScale=1.00¦XCorrection=1.00¦YCorrection=1.00¦PrintKind=0¦BorderSize=5000000¦LeftOffset=0¦BottomOffset=0¦Orientation=2¦PaperLength=1000¦PaperWidth=1000¦Scale=100¦PaperSource=15¦PrintQuality=600¦MediaType=1¦DitherType=10¦PaperKind=Letter¦PrintScaleMode=1
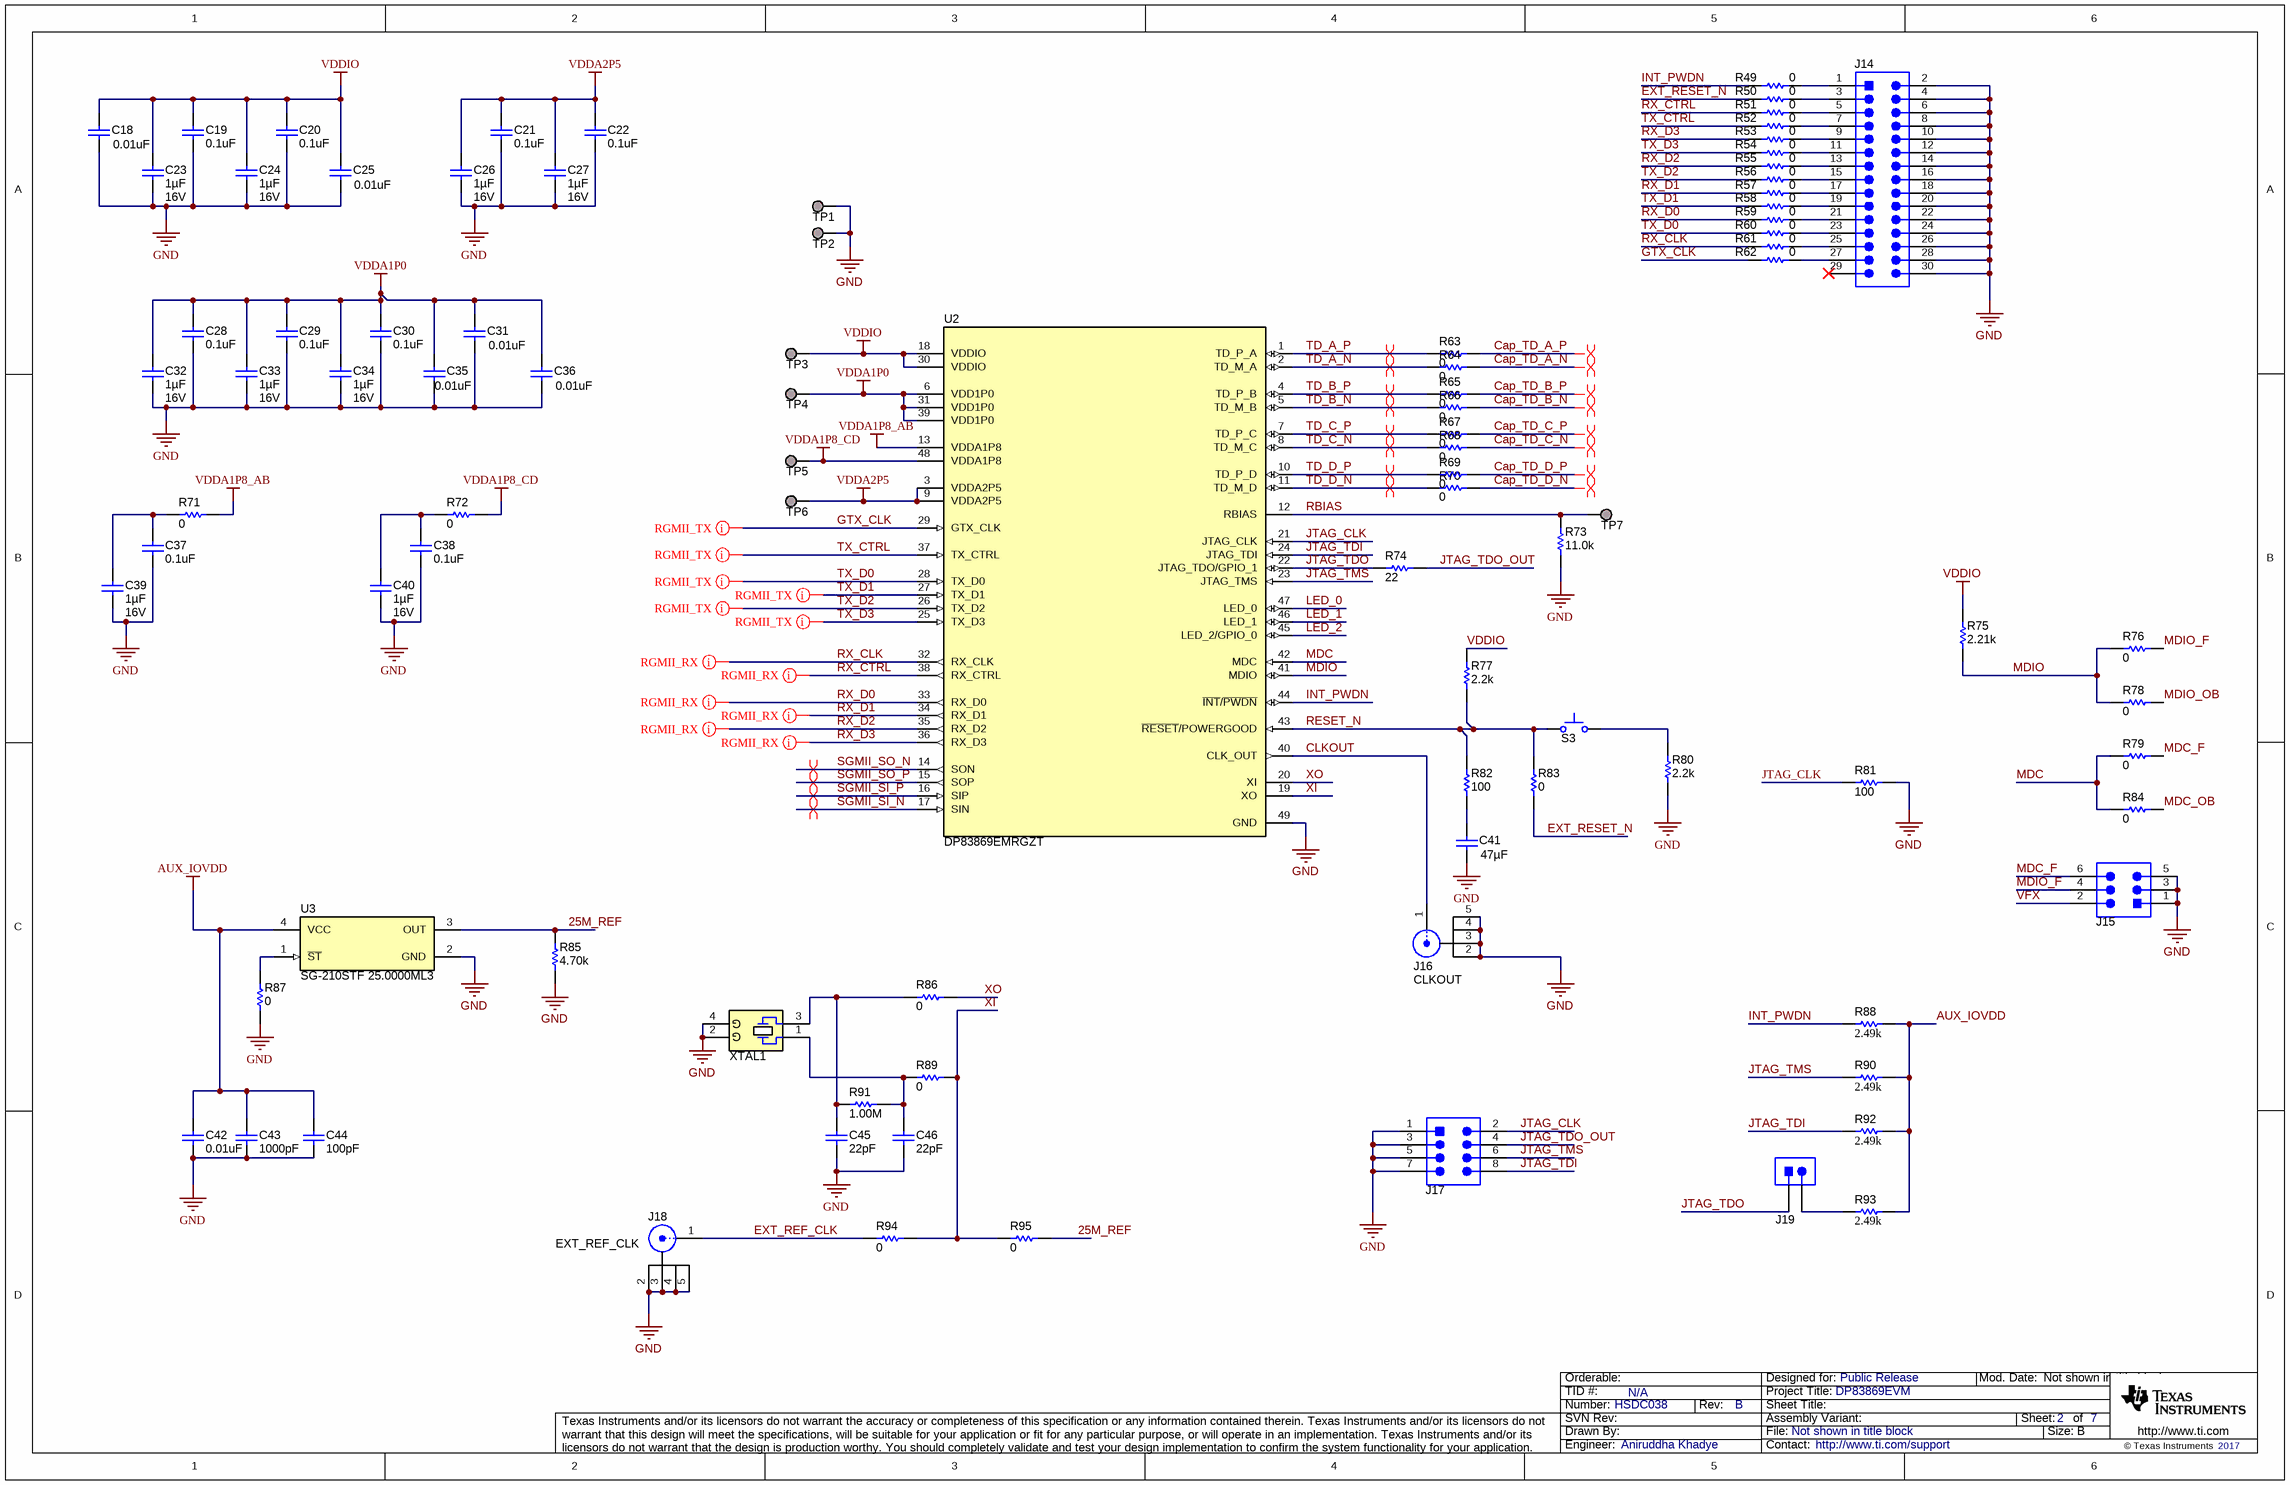
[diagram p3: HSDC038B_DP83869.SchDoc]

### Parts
C18  ValueDisplayed: 0.01uF  [0402]  (hidden comment: GRM155R61C103KA01D)
C19  ValueDisplayed: 0.1uF  [0402]  (hidden comment: C1005X5R1A104K050BA)
C20  ValueDisplayed: 0.1uF  [0402]  (hidden comment: C1005X5R1A104K050BA)
C21  ValueDisplayed: 0.1uF  [0402]  (hidden comment: C1005X5R1A104K050BA)
C22  ValueDisplayed: 0.1uF  [0402]  (hidden comment: C1005X5R1A104K050BA)
C23  ValueDisplayed: 1µF  VDC_V: 16V  [0402]  (hidden comment: GRM155R61C105MA12D)
C24  ValueDisplayed: 1µF  VDC_V: 16V  [0402]  (hidden comment: GRM155R61C105MA12D)
C25  ValueDisplayed: 0.01uF  [0402]  (hidden comment: GRM155R61C103KA01D)
C26  ValueDisplayed: 1µF  VDC_V: 16V  [0402]  (hidden comment: GRM155R61C105MA12D)
C27  ValueDisplayed: 1µF  VDC_V: 16V  [0402]  (hidden comment: GRM155R61C105MA12D)
C28  ValueDisplayed: 0.1uF  [0402]  (hidden comment: C1005X5R1A104K050BA)
C29  ValueDisplayed: 0.1uF  [0402]  (hidden comment: C1005X5R1A104K050BA)
C30  ValueDisplayed: 0.1uF  [0402]  (hidden comment: C1005X5R1A104K050BA)
C31  ValueDisplayed: 0.01uF  [0402]  (hidden comment: GRM155R61C103KA01D)
C32  ValueDisplayed: 1µF  VDC_V: 16V  [0402]  (hidden comment: GRM155R61C105MA12D)
C33  ValueDisplayed: 1µF  VDC_V: 16V  [0402]  (hidden comment: GRM155R61C105MA12D)
C34  ValueDisplayed: 1µF  VDC_V: 16V  [0402]  (hidden comment: GRM155R61C105MA12D)
C35  ValueDisplayed: 0.01uF  [0402]  (hidden comment: GRM155R61C103KA01D)
C36  ValueDisplayed: 0.01uF  [0402]  (hidden comment: GRM155R61C103KA01D)
C37  ValueDisplayed: 0.1uF  [0402]  (hidden comment: C1005X5R1A104K050BA)
C38  ValueDisplayed: 0.1uF  [0402]  (hidden comment: C1005X5R1A104K050BA)
C39  ValueDisplayed: 1µF  VDC_V: 16V  [0402]  (hidden comment: GRM155R61C105MA12D)
C40  ValueDisplayed: 1µF  VDC_V: 16V  [0402]  (hidden comment: GRM155R61C105MA12D)
C41  ValueDisplayed: 47µF  [0805_HV]  (hidden comment: GRM21BC80G476ME15L)
C42  ValueDisplayed: 0.01uF  [0402]  (hidden comment: C0402C103J5RACTU)
C43  ValueDisplayed: 1000pF  [0402]  (hidden comment: C0402C102J3RACTU)
C44  ValueDisplayed: 100pF  [0402]  (hidden comment: CC0402JRNPO9BN101)
C45  ValueDisplayed: 22pF  [0603]  (hidden comment: CGA3E2C0G1H220J080AA)
C46  ValueDisplayed: 22pF  [0603]  (hidden comment: CGA3E2C0G1H220J080AA)
J14  PRPC015DAAN-RC  [Sullins_xxPC015DAAN-RC]  (value not drawn)
J15  90122-0763  [Molex_90122-0763]  (value not drawn)
J16  CLKOUT  [Samtec_MCX-J-P-H-ST-SM1]
J17  TSW-104-07-G-D  [TSW-104-07-G-D]  (value not drawn)
J18  EXT_REF_CLK  [Samtec_MCX-J-P-H-ST-SM1]
J19  HTSW-102-07-G-S  [Samtec_HTSW-102-07-G-S]  (value not drawn)
R49  ValueDisplayed: 0  [0402]  (hidden comment: RC0402JR-070RL)
R50  ValueDisplayed: 0  [0402]  (hidden comment: RC0402JR-070RL)
R51  ValueDisplayed: 0  [0402]  (hidden comment: RC0402JR-070RL)
R52  ValueDisplayed: 0  [0402]  (hidden comment: RC0402JR-070RL)
R53  ValueDisplayed: 0  [0402]  (hidden comment: RC0402JR-070RL)
R54  ValueDisplayed: 0  [0402]  (hidden comment: RC0402JR-070RL)
R55  ValueDisplayed: 0  [0402]  (hidden comment: RC0402JR-070RL)
R56  ValueDisplayed: 0  [0402]  (hidden comment: RC0402JR-070RL)
R57  ValueDisplayed: 0  [0402]  (hidden comment: RC0402JR-070RL)
R58  ValueDisplayed: 0  [0402]  (hidden comment: RC0402JR-070RL)
R59  ValueDisplayed: 0  [0402]  (hidden comment: RC0402JR-070RL)
R60  ValueDisplayed: 0  [0402]  (hidden comment: RC0402JR-070RL)
R61  ValueDisplayed: 0  [0402]  (hidden comment: RC0402JR-070RL)
R62  ValueDisplayed: 0  [0402]  (hidden comment: RC0402JR-070RL)
R63  ValueDisplayed: 0  [0201]  (hidden comment: ERJ-1GN0R00C)
R64  ValueDisplayed: 0  [0201]  (hidden comment: ERJ-1GN0R00C)
R65  ValueDisplayed: 0  [0201]  (hidden comment: ERJ-1GN0R00C)
R66  ValueDisplayed: 0  [0201]  (hidden comment: ERJ-1GN0R00C)
R67  ValueDisplayed: 0  [0201]  (hidden comment: ERJ-1GN0R00C)
R68  ValueDisplayed: 0  [0201]  (hidden comment: ERJ-1GN0R00C)
R69  ValueDisplayed: 0  [0201]  (hidden comment: ERJ-1GN0R00C)
R70  ValueDisplayed: 0  [0201]  (hidden comment: ERJ-1GN0R00C)
R71  ValueDisplayed: 0  [0402]  (hidden comment: MCR01MZPJ000)
R72  ValueDisplayed: 0  [0402]  (hidden comment: MCR01MZPJ000)
R73  ValueDisplayed: 11.0k  [0201M]  (hidden comment: CRCW020111K0FKED)
R74  ValueDisplayed: 22  [0201M]  (hidden comment: ERJ-1GNJ220C)
R75  ValueDisplayed: 2.21k  [TNPW0603]  (hidden comment: TNPW06032K21BEEA)
R76  ValueDisplayed: 0  [0402]  (hidden comment: RC0402JR-070RL)
R77  ValueDisplayed: 2.2k  [0201M]  (hidden comment: CRCW02012K20JNED)
R78  ValueDisplayed: 0  [0402]  (hidden comment: RC0402JR-070RL)
R79  ValueDisplayed: 0  [0402]  (hidden comment: RC0402JR-070RL)
R80  ValueDisplayed: 2.2k  [0201M]  (hidden comment: CRCW02012K20JNED)
R81  ValueDisplayed: 100  [0402]  (hidden comment: ERJ-2RKF1000X)
R82  ValueDisplayed: 100  [0402]  (hidden comment: ERJ-2GEJ101X)
R83  ValueDisplayed: 0  [0201]  (hidden comment: ERJ-1GN0R00C)
R84  ValueDisplayed: 0  [0402]  (hidden comment: RC0402JR-070RL)
R85  ValueDisplayed: 4.70k  [0201_033]  (hidden comment: CRCW02014K70FKED)
R86  ValueDisplayed: 0  [0201]  (hidden comment: ERJ-1GN0R00C)
R87  ValueDisplayed: 0  [0201]  (hidden comment: ERJ-1GN0R00C)
R88  ValueDisplayed: 2.49k  [0402]  (hidden comment: CRCW04022K49FKED)
R89  ValueDisplayed: 0  [0201]  (hidden comment: ERJ-1GN0R00C)
R90  ValueDisplayed: 2.49k  [0402]  (hidden comment: CRCW04022K49FKED)
R91  ValueDisplayed: 1.00M  [0402]  (hidden comment: RC0402FR-071ML)
R92  ValueDisplayed: 2.49k  [0402]  (hidden comment: CRCW04022K49FKED)
R93  ValueDisplayed: 2.49k  [0402]  (hidden comment: CRCW04022K49FKED)
R94  ValueDisplayed: 0  [0201]  (hidden comment: ERJ-1GN0R00C)
R95  ValueDisplayed: 0  [0201]  (hidden comment: ERJ-1GN0R00C)
S3  KSR221GLFS  [KSR]  (value not drawn)
TP1  GND  [Keystone_5019]  (value not drawn)
TP2  GND  [Keystone_5019]  (value not drawn)
TP3  IO  [Keystone_5019]  (value not drawn)
TP4  1.0V  [Keystone_5019]  (value not drawn)
TP5  1.8V  [Keystone_5019]  (value not drawn)
TP6  2.5V  [Keystone_5019]  (value not drawn)
TP7  TESTPOINT  [TP_25MIL-SMT]  (value not drawn)  (no BOM)
U2  DP83869EMRGZT  [RGZ0048B]
U3  SG-210STF 25.0000ML3  [Epson_SG-210]
XTAL1  ECS-250-12-33Q-JES-TR  [ECS_ECS-33Q]  (value not drawn)

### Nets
AUX_IOVDD: C42.2 C43.2 C44.2 R88.2 R90.2 R92.2 R93.2 U3.4(VCC)
GND: C18.2 C19.2 C20.2 C21.2 C22.2 C23.2 C24.2 C25.2 C26.2 C27.2 C28.2 C29.2 C30.2 C31.2 C32.2 C33.2 C34.2 C35.2 C36.2 C37.2 C38.2 C39.2 C40.2 C41.2 C42.1 C43.1 C44.1 C45.2 C46.2 J14.2 J14.4 J14.6 J14.8 J14.10 J14.12 J14.14 J14.16 J14.18 J14.20 J14.22 J14.24 J14.26 J14.28 J14.30 J15.1 J15.3 J15.5 J16.2 J16.3 J16.4 J16.5 J17.1 J17.3 J17.5 J17.7 J18.2 J18.3 J18.4 J18.5 R73.1 R80.1 R81.2 R85.1 R87.2 TP1.1 TP2.1 U2.49(GND) U3.2(GND) XTAL1.2(GND) XTAL1.4(GND)
VDDA1P0: C28.1 C29.1 C30.1 C31.1 C32.1 C33.1 C34.1 C35.1 C36.1 TP4.1 U2.6(VDD1P0) U2.31(VDD1P0) U2.39(VDD1P0)
VDDA1P8_AB: R71.1 U2.13(VDDA1P8)
VDDA1P8_CD: R72.1 TP5.1 U2.48(VDDA1P8)
VDDA2P5: C21.1 C22.1 C26.1 C27.1 TP6.1 U2.3(VDDA2P5) U2.9(VDDA2P5)
VDDIO: C18.1 C19.1 C20.1 C23.1 C24.1 C25.1 R75.2 R77.2 TP3.1 U2.18(VDDIO) U2.30(VDDIO)
VFX: J15.2
25M_REF: R85.2 R95.2 U3.3(OUT)
Cap_TD_A_N: R64.2
Cap_TD_A_P: R63.2
Cap_TD_B_N: R66.2
Cap_TD_B_P: R65.2
Cap_TD_C_N: R68.2
Cap_TD_C_P: R67.2
Cap_TD_D_N: R70.2
Cap_TD_D_P: R69.2
CLKOUT: J16.1 U2.40(CLK_OUT)
EXT_REF_CLK: J18.1 R94.1
EXT_RESET_N: R50.2 R83.1
GTX_CLK: R62.2 U2.29(GTX_CLK)
INT_PWDN: R49.2 R88.1 U2.44(~{INT}/~{PWDN})
JTAG_CLK: J17.2 R81.1 U2.21(JTAG_CLK)
JTAG_TDI: J17.8 R92.1 U2.24(JTAG_TDI)
JTAG_TDO: J19.1 R74.1 U2.22(JTAG_TDO/GPIO_1)
JTAG_TDO_OUT: J17.4 R74.2
JTAG_TMS: J17.6 R90.1 U2.23(JTAG_TMS)
LED_0: U2.47(LED_0)
LED_1: U2.46(LED_1)
LED_2: U2.45(LED_2/GPIO_0)
MDC: R79.2 R84.2 U2.42(MDC)
MDC_F: J15.6 R79.1
MDC_OB: R84.1
MDIO: R75.1 R76.2 R78.2 U2.41(MDIO)
MDIO_F: J15.4 R76.1
MDIO_OB: R78.1
RBIAS: R73.2 TP7.1 U2.12(RBIAS)
RESET_N: R77.1 R82.2 R83.2 S3.1 U2.43(~{RESET}/POWERGOOD)
RX_CLK: R61.2 U2.32(RX_CLK)
RX_CTRL: R51.2 U2.38(RX_CTRL)
RX_D0: R59.2 U2.33(RX_D0)
RX_D1: R57.2 U2.34(RX_D1)
RX_D2: R55.2 U2.35(RX_D2)
RX_D3: R53.2 U2.36(RX_D3)
SGMII_SI_N: U2.17(SIN)
SGMII_SI_P: U2.16(SIP)
SGMII_SO_N: U2.14(SON)
SGMII_SO_P: U2.15(SOP)
TD_A_N: R64.1 U2.2(TD_M_A)
TD_A_P: R63.1 U2.1(TD_P_A)
TD_B_N: R66.1 U2.5(TD_M_B)
TD_B_P: R65.1 U2.4(TD_P_B)
TD_C_N: R68.1 U2.8(TD_M_C)
TD_C_P: R67.1 U2.7(TD_P_C)
TD_D_N: R70.1 U2.11(TD_M_D)
TD_D_P: R69.1 U2.10(TD_P_D)
TX_CTRL: R52.2 U2.37(TX_CTRL)
TX_D0: R60.2 U2.28(TX_D0)
TX_D1: R58.2 U2.27(TX_D1)
TX_D2: R56.2 U2.26(TX_D2)
TX_D3: R54.2 U2.25(TX_D3)
XI: R89.2 R94.2 R95.1 U2.19(XO)
XO: R86.2 U2.20(XI)
NetC37_1: C37.1 C39.1 R71.2
NetC38_1: C38.1 C40.1 R72.2
NetC41_1: C41.1 R82.1
NetC45_1: C45.1 R86.1 R91.1 XTAL1.3
NetC46_1: C46.1 R89.1 R91.2 XTAL1.1
NetJ14_1: J14.1 R49.1
NetJ14_3: J14.3 R50.1
NetJ14_5: J14.5 R51.1
NetJ14_7: J14.7 R52.1
NetJ14_9: J14.9 R53.1
NetJ14_11: J14.11 R54.1
NetJ14_13: J14.13 R55.1
NetJ14_15: J14.15 R56.1
NetJ14_17: J14.17 R57.1
NetJ14_19: J14.19 R58.1
NetJ14_21: J14.21 R59.1
NetJ14_23: J14.23 R60.1
NetJ14_25: J14.25 R61.1
NetJ14_27: J14.27 R62.1
NetJ19_2: J19.2 R93.1
NetR80_2: R80.2 S3.2
NetR87_1: R87.1 U3.1(~{ST})

Not connected (* = marked no-connect by the designer): J14 29*

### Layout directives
differential pair: Cap_TD_A_N, Cap_TD_A_P, Cap_TD_B_N, Cap_TD_B_P, Cap_TD_C_N, Cap_TD_C_P, Cap_TD_D_N, Cap_TD_D_P, SGMII_SI_N, SGMII_SI_P, SGMII_SO_N, SGMII_SO_P, TD_A_N, TD_A_P, TD_B_N, TD_B_P, TD_C_N, TD_C_P, TD_D_N, TD_D_P
net class RGMII_TX: GTX_CLK, TX_CTRL, TX_D0, TX_D1, TX_D2, TX_D3
net class RGMII_RX: RX_CLK, RX_CTRL, RX_D0, RX_D1, RX_D2, RX_D3

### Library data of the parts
C18 C25 C31 C35 C36 = CMP-0006590-2: CAP, CERM, 0.01 uF, 16 V, +/- 10%, X5R, 0402; Manufacturer: MuRata; TaMin_C: -55°C; Polarized: N; SizeAreaWB_mm2: 3; Value1: Unknown; U/M: EA; Value: 0.01uF; TaMax_C: 85°C; SizeZ_mm: 0.6; SizeX_mm: 1; SizeY_mm: 0.5; Value2: 16V; CompType: Capacitor; Cap_F: 10nF; AEC Category: Q200
C19-C22 C28-C30 C37 C38 = CMP-0006259-2: CAP, CERM, 0.1 uF, 10 V, +/- 10%, X5R, 0402; Manufacturer: TDK; Polarized: N; Value: 0.1uF; U/M: EA; Cap_F: 100nF; Value1: Unknown; VDC_V: 10V; TaMin_C: -55°C; TaMax_C: 85°C; AEC Category: Q200; SizeArea_mm2: 0.5; SizeAreaWB_mm2: 3; SizeX_mm: 1; SizeZ_mm: 0.6
C23 C24 C26 C27 C32-C34 C39 C40 = CMP-0084375-1: CAP, CERM, 1 µF, 16 V,+/- 20%, X5R, 0402; Manufacturer: MuRata; Polarized: N; Value: 1uF; U/M: EA; TaMin_C: -55°C; TaMax_C: 85°C; AEC Category: Q200; SizeArea_mm2: 0.5; SizeAreaWB_mm2: 3; SizeX_mm: 1; SizeZ_mm: 0.6
C41 = CMP-0079541-1: CAP, CERM, 47 µF, 4 V,+/- 20%, X6S, 0805; Manufacturer: MuRata; SizeAreaWB_mm2: 6.75; SizeArea_mm2: 2.5; AEC Qualified: N; AEC Category: Q200; Value: 47uF; TaMax_C: 105°C; SizeZ_mm: 1.45; TaMin_C: -55°C; VDC_V: 4V; SizeY_mm: 1.25; U/M: EA; CompType: Capacitor; SizeX_mm: 2; Cap_Case: 0805
C42 = CMP-0006236-2: CAP, CERM, 0.01 uF, 50 V, +/- 5%, X7R, 0402; Manufacturer: Kemet; Polarized: N; Value: 0.01uF; U/M: EA; Cap_F: 10nF; Value1: Unknown; VDC_V: 50V; TaMin_C: -55°C; TaMax_C: 125°C; AEC Category: Q200; SizeArea_mm2: 0.5; SizeAreaWB_mm2: 3; SizeX_mm: 1; SizeZ_mm: 0.6
C43 = CMP-0006234-2: CAP, CERM, 1000 pF, 25 V, +/- 5%, X7R, 0402; Manufacturer: Kemet; Polarized: N; Value: 1000pF; U/M: EA; Cap_F: 1nF; Value1: Unknown; VDC_V: 25V; TaMin_C: -55°C; TaMax_C: 125°C; AEC Category: Q200; SizeArea_mm2: 0.5; SizeAreaWB_mm2: 3; SizeX_mm: 1; SizeZ_mm: 0.6
C44 = CMP-0006303-2: CAP, CERM, 100 pF, 50 V, +/- 5%, C0G/NP0, 0402; Manufacturer: Yageo America; Polarized: N; Value: 100pF; U/M: EA; Value1: Unknown; VDC_V: 50V; TaMin_C: -55°C; TaMax_C: 125°C; AEC Category: Q200; SizeArea_mm2: 0.5; SizeAreaWB_mm2: 3; SizeX_mm: 1; SizeZ_mm: 0.6
C45 C46 = CMP-0007071-4: CAP, CERM, 22 pF, 50 V, +/- 5%, C0G/NP0, AEC-Q200 Grade 1, 0603; Manufacturer: TDK; Polarized: N; Value: 22pF; U/M: EA; Value1: Unknown; VDC_V: 50V; TaMin_C: -55°C; TaMax_C: 125°C; SizeArea_mm2: 1.28; SizeAreaWB_mm2: 4.68; SizeX_mm: 1.6; SizeY_mm: 0.8; SizeZ_mm: 1; AEC Category: Q200; AEC Qualified: Y
J14 = CMP-0080723-1: Header, 2.54mm, 15x2, Gold, TH; Manufacturer: Sullins Connector Solutions; Pitch_mm: 2.54; Gender: Male; Cert_UL: Y; Current_A: 3A; Voltage_V: 1kV; Shrouded: N; Row_Count: 2
J15 = CMP-0077741-1: Header, 2.54mm, 3x2, Gold, R/A, TH; Manufacturer: Molex; Pitch_mm: 2.54; Gender: Male; Cert_UL: Y; Current_A: 3A; Voltage_V: 350V; Shrouded: N; Row_Count: 2
J16 J18 = CMP-0075480-1: Mini-RFCable Connector 50 Ohm; PartNumber: MCX–J–P–H–ST–SM1; Manufacturer: Samtec; CompType: Receptacle; CNHeader: False
J17 = CMP-0075408-1: Header, 100mil, 4x2, Gold, TH; Manufacturer: Samtec; Cert_CSA: Y; Cert_CULUS: N; CNHeader: True; CT: False; Current_A: 6.3A; Gender: Male; Green_Lifecycle: Active; Green_REACh: Passed; Pitch_mm: 2.54; Row_Count: 2; Voltage_V: 550V
J19 = CMP-0075483-1: as J6 on sheet HSDC038B_Configuration_Pins
R49-R62 R76 R78 R79 R84 = CMP-0027004-2: RES, 0, 5%, 0.063 W, 0402; Manufacturer: Yageo America; Value: 0; Value_Code: 0000; Power_W: 63mW; Value2: 0.063W; VDC_V: 50V; TempCo: 200 ppm/C; EIA_Code: E24; U/M: EA; AEC Category: Q200; SizeArea_mm2: 0.5; SizeX_mm: 1; SizeZ_mm: 0.6
R63-R70 R83 R86 R87 R89 R94 R95 = CMP-0065361-1: RES, 0, 5%, .05 W, AEC-Q200 Grade 0, 0201; Manufacturer: Panasonic; Value: 0; Value_Code: 0000; Power_W: 50mW; Value2: .05W; TempCo: ppm/C; EIA_Code: E24; U/M: EA; AEC Category: Q200; AEC Qualified: Y; SizeArea_mm2: 0.18; SizeX_mm: 0.6; SizeY_mm: 0.3; SizeZ_mm: 0.26; Green_Lifecycle: Not Set; Green_REACh: Incomplete
R71 R72 = CMP-0027002-2: as R31 on sheet HSDC038B_Configuration_Pins
R73 = CMP-0027263-3: RES, 11.0 k, 1%, 0.05 W, 0201; Manufacturer: Vishay-Dale; Value: 11.0k; Res_ohm: 11k; Value_Code: 11k0; Power_W: 50mW; Value2: 0.05W; VDC_V: 30V; TempCo: 200 ppm/C; EIA_Code: E96; AEC Category: Q200; AEC Qualified: N; SizeArea_mm2: 0.18; SizeX_mm: 0.6; SizeY_mm: 0.3; SizeZ_mm: 0.26
R74 = CMP-0027015-3: RES, 22, 5%, 0.05 W, AEC-Q200 Grade 1, 0201; Manufacturer: Panasonic; Value: 22; Value_Code: 22R0; Power_W: 50mW; Value2: 0.05W; TempCo: 200 ppm/C; EIA_Code: E24; U/M: EA; AEC Category: Q200; AEC Grade: 1; AEC Qualified: Y; SizeArea_mm2: 0.18; SizeX_mm: 0.6; SizeY_mm: 0.3; SizeZ_mm: 0.26
R75 = CMP-0025690-1: RES, 2.21 k, 0.1%, 0.1 W, AEC-Q200 Grade 0, 0603; Manufacturer: Vishay-Dale; Value: 2.21k; Value_Code: 2k21; Power_W: 100mW; Value2: 0.1W; VDC_V: 75V; TempCo: 25 ppm/C; EIA_Code: E192; U/M: EA; AEC Category: Q200; AEC Qualified: Y; AEC Grade: 0; SizeArea_mm2: 1.36; SizeX_mm: 1.6; SizeY_mm: 0.85; SizeZ_mm: 0.55
R77 R80 = CMP-0027010-2: RES, 2.2 k, 5%, 0.05 W, 0201; Manufacturer: Vishay-Dale; Value: 2.2k; Value_Code: 2k20; Power_W: 50mW; Value2: 0.05W; VDC_V: 30V; TempCo: 200 ppm/C; EIA_Code: E24; AEC Category: Q200; AEC Qualified: N; SizeArea_mm2: 0.18; SizeX_mm: 0.6; SizeY_mm: 0.3; SizeZ_mm: 0.26
R81 = CMP-0026656-1: RES, 100, 1%, 0.1 W, 0402; Manufacturer: Panasonic; Power_W: 100mW; TempCo: 100 ppm/C; Value_Code: 100R; U/M: EA; Value: 100; EIA_Code: E96; SizeX_mm: 1; SizeY_mm: 0.5; SizeZ_mm: 0.6; Value2: 0.1W; VDC_V: 50V; AEC Category: Q200
R82 = CMP-0026993-2: RES, 100, 5%, 0.1 W, AEC-Q200 Grade 0, 0402; Manufacturer: Panasonic; Power_W: 100mW; TempCo: 200 ppm/C; Value_Code: 100R; U/M: EA; Value: 100; EIA_Code: E24; SizeX_mm: 1; SizeY_mm: 0.5; SizeZ_mm: 0.6; Value2: 0.1W; AEC Qualified: Y; AEC Grade: 0; AEC Category: Q200
R85 = CMP-0027280-3: RES, 4.70 k, 1%, 0.05 W, 0201; Manufacturer: Vishay-Dale; Value: 4.70k; Res_ohm: 4.7k; Value_Code: 4k70; Power_W: 50mW; Value2: 0.05W; VDC_V: 30V; TempCo: 100 ppm/C; AEC Category: Q200; AEC Qualified: N; SizeArea_mm2: 0.18; SizeX_mm: 0.6; SizeY_mm: 0.3; SizeZ_mm: 0.33
R88 R90 R92 R93 = CMP-0026237-2: as R19 on sheet HSDC038B_Configuration_Pins
R91 = CMP-0026727-1: RES, 1.00 M, 1%, 0.063 W, 0402; Manufacturer: Yageo America; Value: 1.00Meg; Res_ohm: 1M; Value_Code: 1M00; Power_W: 63mW; Value2: 0.063W; TempCo: 100 ppm/C; EIA_Code: E96; U/M: EA; AEC Category: Q200; SizeArea_mm2: 0.5; SizeX_mm: 1; SizeZ_mm: 0.6
S3 = CMP-0002170-2: as S2 on sheet HSDC038B_COMS
TP1-TP6 = CMP-0055162-1: Test Point, Miniature, SMT; Manufacturer: Keystone; PartNumber: 5019; CNHeader: FALSE; Green_Lifecycle: Active; Green_REACh: Passed; CT: TRUE
TP7 = CMP-0078143-2: TEST POINT.  No entry in BOM.
U2 = CMP-0079810-3: Robust, High Immunity 10/100/1000 Ethernet Physical Layer Transceiver, RGZ0048B (VQFN-48); Manufacturer: Texas Instruments; SizeAreaWB_mm2: 81; SizeArea_mm2: 49; AEC Qualified: N; AEC Category: Q200; SizeZ_mm: 1; SizeY_mm: 7; CompType: IC
U3 = CMP-0084386-1: Oscillator, 25 MHz, SMD; Manufacturer: Epson; TaMin_C: -40°C; TaMax_C: 85°C; Frequency Stability: 50 ppm; AEC Category: Q200; AEC Qualified: N; Frequency_Fixed: 25MHz
XTAL1 = CMP-0079863-1: Crystal, 25 MHz, 20 ppm, AEC-Q200 Grade 1, SMD; Manufacturer: ECS Inc.; TaMin_C: -55°C; Frequency Tolerance: 20 ppm; Frequency Stability: 50 ppm; SizeAreaWB_mm2: 14.7; Frequency_Fixed: 25MHz; TaMax_C: 125°C; SizeZ_mm: 0.8; SizeX_mm: 2.5; SizeY_mm: 3.2; SizeArea_mm2: 8; AEC Qualified: Y; AEC Grade: 1; AEC Category: Q200

## Sheet HSDC038B_Hardware.SchDoc
size 431 x 279 mm; Date: Not shown in title block; ApprovedBy: Not shown in title block; CheckedBy: Not shown in title block; Author: Not shown in title block; CompanyName: Not shown in title block; Engineer: Not shown in title block; Organization: Not shown in title block; Address1: Not shown in title block; Address2: Not shown in title block; Address3: Not shown in title block; Address4: Not shown in title block; DocumentNumber: 7; Revision: Use project parameter SCH_Rev; SheetNumber: 7; SheetTotal: 7; PageSetup: Record=PageOptions¦CenterHorizontal=True¦CenterVertical=True¦PrintScale=1.00¦XCorrection=1.00¦YCorrection=1.00¦PrintKind=0¦BorderSize=5000000¦LeftOffset=0¦BottomOffset=0¦Orientation=2¦PaperLength=1000¦PaperWidth=1000¦Scale=100¦PaperSource=15¦PrintQuality=600¦MediaType=1¦DitherType=10¦PaperKind=Letter¦PrintScaleMode=1
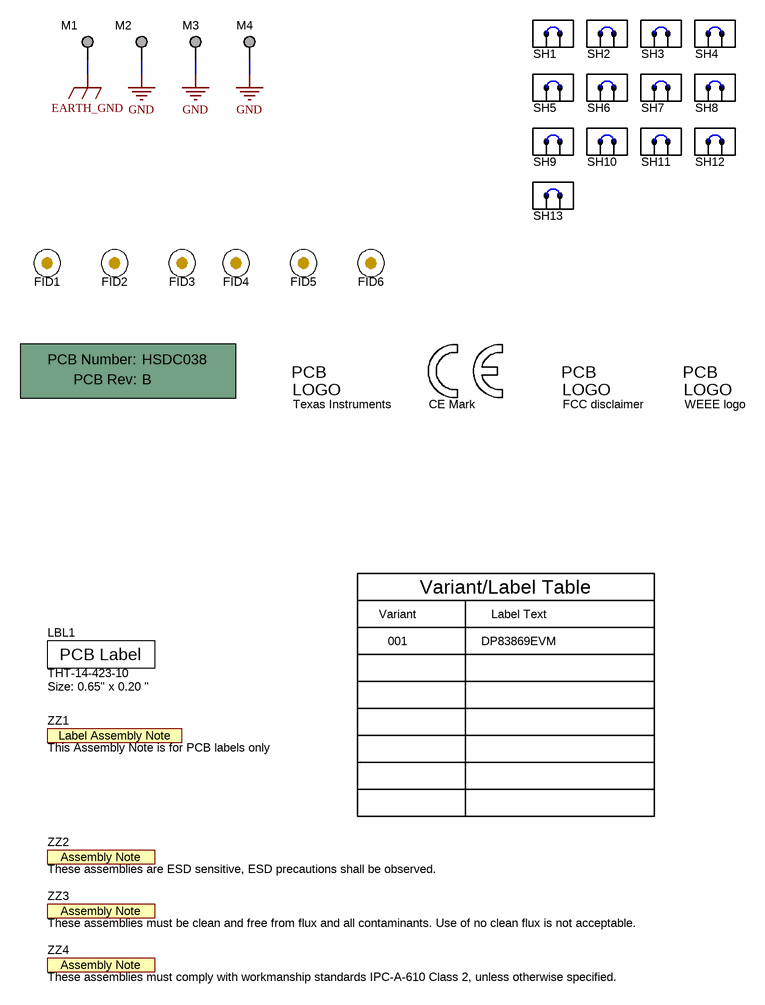
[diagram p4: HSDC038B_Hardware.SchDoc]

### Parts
!PCB1  Printed Circuit Board  (value not drawn)  (mechanical)
FID1  Fiducial  [Fiducial10-20]  (value not drawn)
FID2  Fiducial  [Fiducial10-20]  (value not drawn)
FID3  Fiducial  [Fiducial10-20]  (value not drawn)
FID4  Fiducial  [Fiducial10-20]  (value not drawn)
FID5  Fiducial  [Fiducial10-20]  (value not drawn)
FID6  Fiducial  [Fiducial10-20]  (value not drawn)
LBL1  THT-14-423-10  Note: Size: 0.65" x 0.20 "  [Label_650x200]
Logo1  CE Mark  [CE_Mark_5mm]  (no BOM)
Logo2  Texas Instruments  [TI_Stacked_Overlay_Small]  (no BOM)
Logo3  FCC disclaimer  [FCC_disclaimer]  (no BOM)
Logo4  WEEE logo  [WEEE_Minimum]  (no BOM)
M1  TESTPOINT  [TESTPOINT]  (value not drawn)  (no BOM)
M2  TESTPOINT  [TESTPOINT]  (value not drawn)  (no BOM)
M3  TESTPOINT  [TESTPOINT]  (value not drawn)  (no BOM)
M4  TESTPOINT  [TESTPOINT]  (value not drawn)  (no BOM)
SH1  969102-0000-DA  [SNT-100-BK-G]  (value not drawn)
SH2  969102-0000-DA  [SNT-100-BK-G]  (value not drawn)
SH3  969102-0000-DA  [SNT-100-BK-G]  (value not drawn)
SH4  969102-0000-DA  [SNT-100-BK-G]  (value not drawn)
SH5  969102-0000-DA  [SNT-100-BK-G]  (value not drawn)
SH6  969102-0000-DA  [SNT-100-BK-G]  (value not drawn)
SH7  969102-0000-DA  [SNT-100-BK-G]  (value not drawn)
SH8  969102-0000-DA  [SNT-100-BK-G]  (value not drawn)
SH9  969102-0000-DA  [SNT-100-BK-G]  (value not drawn)
SH10  969102-0000-DA  [SNT-100-BK-G]  (value not drawn)
SH11  969102-0000-DA  [SNT-100-BK-G]  (value not drawn)
SH12  969102-0000-DA  [SNT-100-BK-G]  (value not drawn)
SH13  969102-0000-DA  [SNT-100-BK-G]  (value not drawn)
ZZ1  This Assembly Note is for PCB labels only  [AssemblyNoteLabel]  (no BOM)
ZZ2  These assemblies are ESD sensitive, ESD precautions shall be observed.  [AssemblyNote]  (no BOM)
ZZ3  These assemblies must be clean and free from flux and all contaminants. Use of no clean flux is not acceptable.  [AssemblyNote]  (no BOM)
ZZ4  These assemblies must comply with workmanship standards IPC-A-610 Class 2, unless otherwise specified.  [AssemblyNote]  (no BOM)

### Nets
EARTH_GND: M1.1
GND: M2.1 M3.1 M4.1

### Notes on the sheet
- Variant
- Variant/Label Table
- Label Text
- 001
- DP83869EVM

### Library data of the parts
!PCB1 = CMP-0003618-2: Manufacturer: Any; PartNumber: HSDC038
FID1-FID6 = CMP-0077181-1: Fiducial mark.  There is nothing to buy or mount.
LBL1 = CMP-0003625-1: Thermal Transfer Printable Labels, 0.650" W x 0.200" H - 10,000 per roll; Manufacturer: Brady; CompType: Label
Logo1 = CMP-0074844-1: SymbolCreator: a0412235
Logo2 = CMP-0074838-1: Texas Instrument Corporate Signature; SymbolCreator: a0412235; Lib Reference: TI_Logo; Library Reference: Logo
Logo3 = CMP-0074847-1: FCC_disclaimer; Library Reference: Logo
Logo4 = CMP-0074769-1
M1-M4 = CMP-0078143-2: TEST POINT.  No entry in BOM.
SH1-SH13 = CMP-0003614-1: Shunt, 100mil, Gold plated, Black; Alternate Manufacturer: Samtec; Manufacturer: 3M; Value: 1x2
ZZ1 = CMP-0003616-3
ZZ2 = CMP-0077236-1
ZZ3 = CMP-0077237-1
ZZ4 = CMP-0077238-1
